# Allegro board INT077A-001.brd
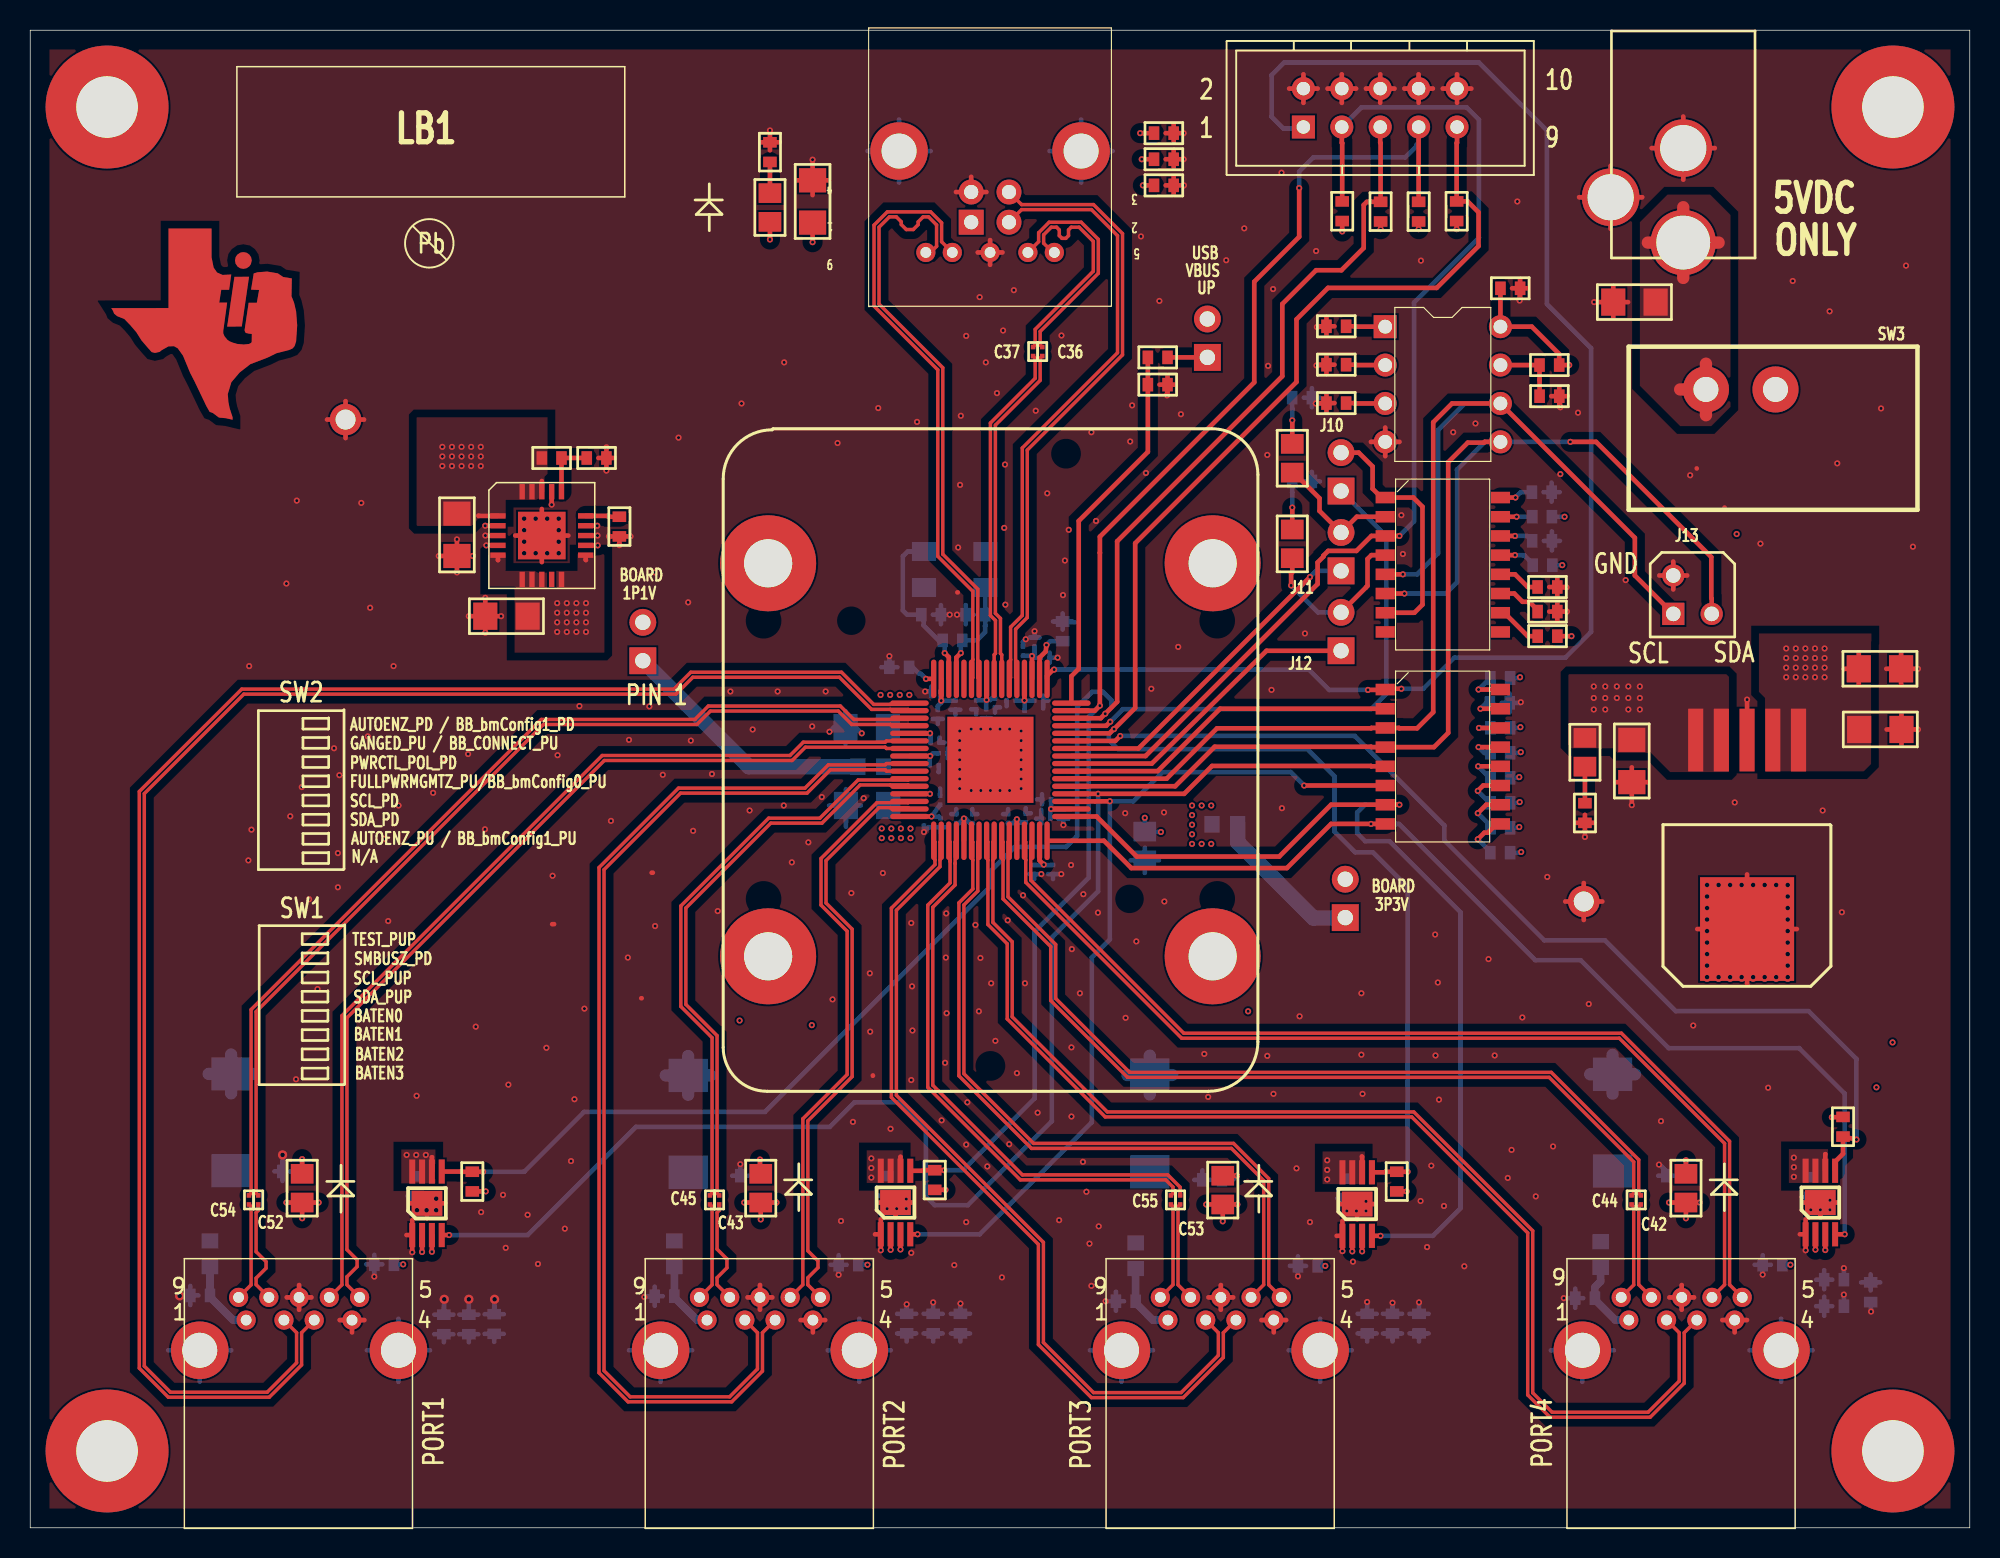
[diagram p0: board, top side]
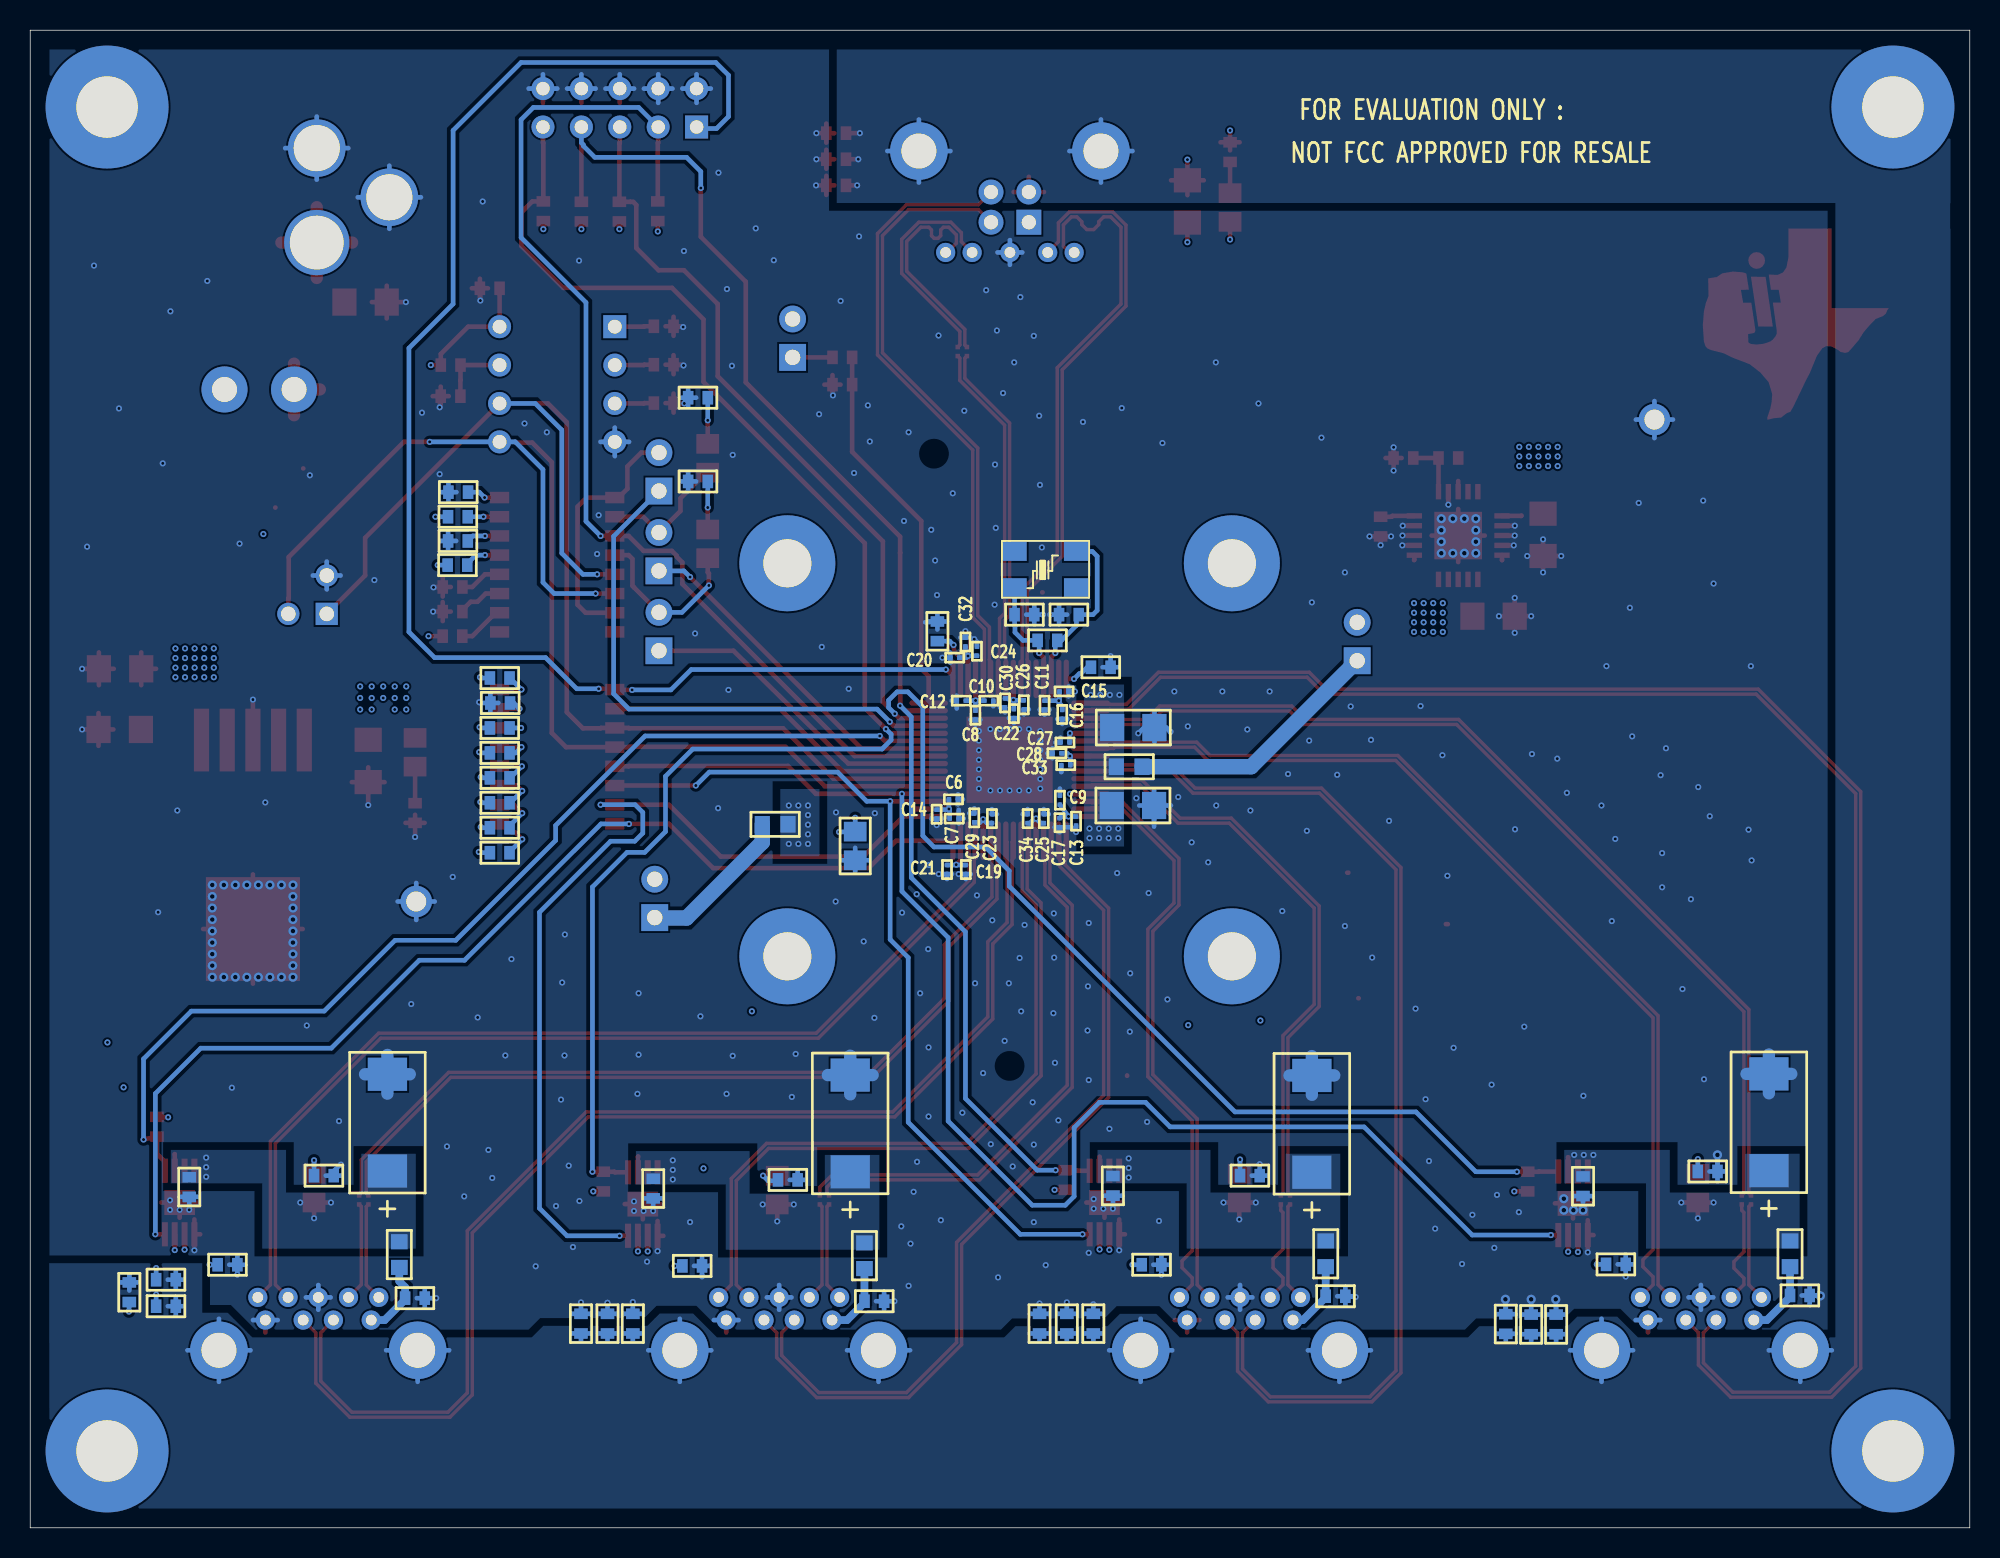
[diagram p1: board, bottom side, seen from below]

Outline 128.27 x 99.06 mm; copper layers: TOP, L2_GND, L3_VCC, BOTTOM. Coordinates in mm from the lower left corner of the outline.
Outline path: 0,99.06 0,0 128.27,0 128.27,99.06 0,99.06

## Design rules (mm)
net group DIFFPAIR0: nets USB_DM_UP USB_DP_UP
net group DIFFPAIR2: nets CAP_UP_TXM CAP_UP_TXP
net group DIFFPAIR3: nets USB_SSTXM_UP USB_SSTXP_UP
net group DIFFPAIR4: nets CAP_DN_TXM1 CAP_DN_TXP1
net group DIFFPAIR5: nets USB_SSTXM_DN1 USB_SSTXP_DN1
net group DIFFPAIR6: nets USB_SSRXM_DN1 USB_SSRXP_DN1
net group DIFFPAIR7: nets USB_DM_DN1 USB_DP_DN1
net group DIFFPAIR8: nets CAP_DN_TXM2 CAP_DN_TXP2
net group DIFFPAIR9: nets USB_SSTXM_DN2 USB_SSTXP_DN2
net group DIFFPAIR10: nets USB_SSRXM_DN2 USB_SSRXP_DN2
net group DIFFPAIR11: nets USB_DM_DN2 USB_DP_DN2
net group DIFFPAIR12: nets CAP_DN_TXM3 CAP_DN_TXP3
net group DIFFPAIR13: nets USB_SSTXM_DN3 USB_SSTXP_DN3
net group DIFFPAIR14: nets USB_SSRXM_DN3 USB_SSRXP_DN3
net group DIFFPAIR15: nets USB_DM_DN3 USB_DP_DN3
net group DIFFPAIR16: nets CAP_DN_TXM4 CAP_DN_TXP4
net group DIFFPAIR17: nets USB_SSTXM_DN4 USB_SSTXP_DN4
net group DIFFPAIR18: nets USB_SSRXM_DN4 USB_SSRXP_DN4
net group DIFFPAIR19: nets USB_DM_DN4 USB_DP_DN4
net group DIFFPAIR20: nets USB_SSRXN_UP USB_SSRXP_UP

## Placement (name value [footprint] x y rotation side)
C1  18pF  [0402]  63.17 60.4 180 bottom
C2  18pF  [0402]  58.93 60.4 0 bottom
C3  1uF  [0402]  68.28 58.65 90 bottom
C4  0.1uF  [0402]  97.23 81.99 0 top
C5  1uF  [0805]  73.71 46.05 270 bottom
C6  0.001uF  [0201]  67.51 48.18 180 bottom
C7  0.01uF  [0201]  67.46 46.91 180 bottom
C8  0.1uF  [0201]  65.76 54.05 270 bottom
C9  0.001uF  [0201]  60.17 47.83 90 bottom
C10  0.01uF  [0201]  65.18 54.71 180 bottom
C11  0.1uF  [0201]  61.19 54.71 270 bottom
C12  0.001uF  [0201]  66.4 54.71 0 bottom
C13  0.01uF  [0201]  59.11 47.04 270 bottom
C14  0.1uF  [0201]  68.33 47.5 270 bottom
C15  0.001uF  [0201]  60.2 55.32 180 bottom
C16  0.01uF  [0201]  60.02 54.1 270 bottom
C17  0.1uF  [0201]  60.2 46.94 270 bottom
C18  10uF  [1206]  56.72 52.93 180 bottom
C19  0.001uF  [0201]  66.4 43.84 270 bottom
C20  0.01uF  [0201]  66.83 57.56 0 bottom
C21  0.1uF  [0201]  67.64 43.84 270 bottom
C22  0.001uF  [0201]  63.22 54.15 270 bottom
C23  0.01uF  [0201]  64.67 46.61 90 bottom
C24  0.1uF  [0201]  65.66 57.68 90 bottom
C25  0.001uF  [0201]  61.24 46.61 90 bottom
C26  0.01uF  [0201]  62.56 54.74 270 bottom
C27  0.1uF  [0201]  59.54 51.94 0 bottom
C28  0.001uF  [0201]  60.07 51.23 0 bottom
C29  0.01uF  [0201]  65.84 46.66 90 bottom
C30  0.1uF  [0201]  63.8 54.86 270 bottom
C31  10uF  [1206]  56.74 47.78 180 bottom
C32  0.001uF  [0201]  66.42 58.29 90 bottom
C33  0.01uF  [0201]  59.49 50.44 0 bottom
C34  0.1uF  [0201]  62.31 46.61 90 bottom
C35  10uF  [1206]  51.74 86.33 90 top
C36  0.1uF 0201  [0201]  66.32 78.1 270 top
C37  0.1uF 0201  [0201]  66.93 78.1 270 top
C38  0.1uF  [0402]  74.32 92.25 0 top
C39  0.001uF  [0402]  74.32 90.53 0 top
C40  0.1uF  [0402]  103.48 15.19 180 bottom
C41  0.1uF  [0402]  42.6 15.32 180 bottom
C42  0.1uF 0201  [0201]  106.51 21.39 90 top
C43  0.1uF 0201  [0201]  45.56 21.39 90 top
C44  0.1uF 0201  [0201]  105.91 21.39 90 top
C45  0.1uF 0201  [0201]  44.95 21.39 90 top
C46  0.1uF  [0402]  118.64 14.66 0 bottom
C47  0.001uF  [0402]  118.64 16.41 0 bottom
C48  0.1uF  [0402]  57.96 12.85 90 bottom
C49  0.001uF  [0402]  59.72 12.85 90 bottom
C50  0.1uF  [0402]  11.89 15.37 180 bottom
C51  0.1uF  [0402]  73.1 14.99 180 bottom
C52  0.1uF 0201  [0201]  15.08 21.39 90 top
C53  0.1uF 0201  [0201]  76.05 21.39 90 top
C54  0.1uF 0201  [0201]  14.47 21.39 90 top
C55  0.1uF 0201  [0201]  75.44 21.39 90 top
C56  0.1uF  [0402]  30.68 12.83 90 bottom
C57  0.001uF  [0402]  29.01 12.8 90 bottom
C58  0.1uF  [0402]  90.09 12.85 90 bottom
C59  0.001uF  [0402]  88.42 12.85 90 bottom
C61  10uF  [1206]  107.49 81.08 180 top
C66  0.1uF  [0402]  24.05 17.42 180 bottom
C67  10uF  [1206]  120.95 52.81 0 top
C68  10uF  [1206]  105.92 52.12 270 top
C69  0.1uF  [0402]  25.58 23.24 270 bottom
C70  150uF  [7343]  13.28 23.62 90 bottom
C71  150uF  [7343]  43.51 23.52 90 bottom
C72  0.1uF  [0402]  56.67 23.27 270 bottom
C73  10uF  [1206]  32.89 60.3 180 top
C74  10uF  [1206]  28.22 67.08 270 top
C75  0.1uF  [0402]  54.76 17.4 180 bottom
C76  150uF  [7343]  74.04 23.55 90 bottom
C77  0.1uF  [0402]  87.07 23.09 270 bottom
C78  0.1uF  [0402]  85.14 17.32 180 bottom
C79  150uF  [7343]  104.65 23.6 90 bottom
C80  0.1uF  [0402]  117.75 23.19 270 bottom
C81  0.1uF  [0402]  115.87 17.4 180 bottom
C82  10uF  [1206]  120.93 56.82 0 top
D1  LED Green 0805  [0805]  48.92 86.39 90 top
D2  LED-DNI  [0805]  83.46 64.13 90 top
D3  LED-DNI  [0805]  83.46 69.8 90 top
D4  LED Green 0805  [0805]  102.82 52.25 270 top
D5  LED Green 0805  [0805]  17.98 21.51 90 top
D6  LED Green 0805  [0805]  48.31 21.51 90 top
D7  LED Green 0805  [0805]  78.87 21.39 90 top
D8  LED Green 0805  [0805]  109.5 21.51 90 top
FB1  220 @ 100MHZ  [0603]  78.16 46.53 0 bottom
FB2  220 @ 100MHZ  [0603]  56.44 50.34 180 bottom
FB3  220 @ 100MHZ  [0603]  103.86 17.22 90 bottom
FB4  220 @ 100MHZ  [0603]  42.6 17.27 90 bottom
FB5  220 @ 100MHZ  [0603]  11.89 17.27 90 bottom
FB6  220 @ 100MHZ  [0603]  73.1 17.14 90 bottom
GND1  TEST POINT  [TESTLOOP]  20.85 73.3 0 top
GND2  TEST POINT  [TESTLOOP]  102.74 41.43 0 top
J1  USB3_TYPEB_CONNECTOR  [USB3_TYPEB_AK4AA009]  62.23 86.36 180 top
J2  USB3_TYPEA_CONNECTOR  [USB3_TYPEA]  109.22 15.24 0 top
J3  USB3_TYPEA_CONNECTOR  [USB3_TYPEA]  48.26 15.24 0 top
J4  USB3_TYPEA_CONNECTOR  [USB3_TYPEA]  17.78 15.24 0 top
J5  USB3_TYPEA_CONNECTOR  [USB3_TYPEA]  78.74 15.24 0 top
J6  2.1mm x 5.5mm  [PJ-202AH]  109.32 85.01 180 top
J7  Header 1x2  [HDR_2X1]  86.97 40.36 0 top
J8  Header 1x2  [HDR_2X1]  77.85 77.42 0 top
J9  Header 1x2  [HDR_2X1]  40.51 57.35 0 top
J10  Header 1x2  [HDR_2X1]  86.69 68.58 0 top
J11  Header 1x2  [HDR_2X1]  86.69 63.3 0 top
J12  Header 1x2  [HDR_2X1]  86.69 58.01 0 top
J13  Header 1x2  [HDR_THVT_3PIN_100]  108.66 62.99 0 top
JP6  Conn 2x5 shroud  [EPRT-CONN-00002-0001]  84.2 92.66 0 top
NOREF  -  []  0 0 90 top
NOREF#2  -  [unnamed#2]  5.08 93.98 0 top
NOREF#3  -  []  11.35 79.3 0 top
NOREF#4  -  [unnamed#2]  5.08 5.08 0 top
NOREF#5  -  []  0 99.06 0 top
NOREF#6  -  [unnamed#2]  123.19 5.08 0 top
NOREF#7  -  [unnamed#2]  123.19 93.98 0 top
R1  1M  [0402]  61.65 58.7 180 bottom
R2  90.9K  [0402]  73.91 77.42 0 top
R3  10K  [0402]  73.91 75.62 0 top
R4  1K  [0402]  96.57 52.91 0 bottom
R5  1K  [0402]  96.57 51.26 0 bottom
R6  4.7K  [0402]  96.57 49.61 0 bottom
R7  4.7K  [0402]  96.57 47.96 0 bottom
R8  4.7K  [0402]  96.57 46.3 0 bottom
R9  4.7K  [0402]  96.57 44.65 0 bottom
R10  NOPOP  [0402]  101.12 76.91 180 top
R11  1K  [0402]  85.72 79.48 0 top
R12  1K  [0402]  85.72 76.94 0 top
R13  1K  [0402]  85.72 74.4 0 top
R14  1K  [0402]  99.82 74.85 0 top
R15  1M  [0402]  74.32 88.8 0 top
R16  330  [0402]  48.92 90.35 90 top
R17  1M  [0402]  121.72 16.23 270 bottom
R18  1M  [0402]  61.52 12.85 90 bottom
R19  1M  [0402]  27.36 12.8 90 bottom
R20  1M  [0402]  91.85 12.85 90 bottom
R21  9.53K  [0402]  56.82 56.92 0 bottom
R22  1K  [0402]  96.57 56.21 0 bottom
R23  1K  [0402]  99.31 68.5 0 bottom
R24  1K  [0402]  97.84 54.56 180 bottom
R25  1K  [0402]  99.34 66.88 0 bottom
R26  10K  [0402]  29.24 22.25 90 top
R27  10K  [0402]  59.82 22.35 90 top
R28  330  [0402]  102.82 47.93 270 top
R29  10K  [0402]  90.37 22.25 90 top
R30  330  [0402]  17.98 23.57 180 bottom
R31  330  [0402]  48.26 23.29 180 bottom
R32  NOPOP  [0402]  38.96 66.88 270 top
R33  1.87K  [0402]  33.83 70.76 0 top
R34  4.99K  [0402]  36.8 70.76 0 top
R35  330  [0402]  78.82 23.01 180 bottom
R36  10K  [0402]  119.89 27.18 270 top
R37  330  [0402]  109.5 23.29 180 bottom
R38  1K  [0402]  99.36 63.68 0 bottom
R39  1K  [0402]  100.63 65.28 180 bottom
R40  330 - DNI  [0402]  84.76 74.75 180 bottom
R41  330 - DNI  [0402]  84.76 69.22 180 bottom
R42  NOPOP  [0402]  86.77 86.44 90 top
R43  NOPOP  [0402]  89.31 86.41 90 top
R44  NOPOP  [0402]  91.82 86.41 90 top
R45  NOPOP  [0402]  94.34 86.44 90 top
R46  1K  [0402]  100.99 60.6 180 top
R47  1K  [0402]  100.99 62.23 180 top
R48  1K  [0402]  99.69 58.98 0 top
SW1  8-POS 50-MIL SMT  [TDA08H0SK1]  93.42 51 270 top
SW2  8-POS 50-MIL SMT  [TDA08H0SK1]  93.42 63.7 270 top
SW3  L101011MS02Q  [L101_SWITCH]  111.02 70.97 270 top
U1  TUSB8044  [GEM050-0064BJ02]  63.5 50.8 0 top
U2  AT24C04  [DIP8]  89.61 79.45 0 top
U4  TPS7A4533  [KTT_6PIN]  118.69 55.02 270 top
U6  TPS74801RGW  [RGW20]  33.83 65.63 0 top
U7  TPS2001C  [DGN8]  26.24 21.46 90 top
U8  TPS2001C  [DGN8]  57.23 21.51 90 top
U9  TPS2001C  [DGN8]  87.76 21.41 90 top
U10  TPS2001C  [DGN8]  118.39 21.51 90 top
Y1  ECS-24MHZ  [ECX-53B]  61.32 63.3 180 bottom

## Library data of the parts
C1-C59 C61 C66-C69 C72-C75 C77 C78 C80-C82 = CAP NP
C70 C71 C76 C79 = CAPACITOR POL
D1-D8 = DIODE
FB1-FB6 = FERRITE BEAD
GND1 GND2 = Test Point Small
J1 = USB3_TYPEB_CONNECTOR
J2-J5 = USB3_TYPEA_CONNECTER
J6 = BNC_2
J7-J12 = HDR2X1 M .1
J13 = HDR2X1 M _0.1
JP6 = eprt-conn-00002-0000
R1-R48 = R
SW1 SW2 = SW DIP-8/SM_0
SW3 = SW SPST
U1 = TUSB8040_41
U2 = AT24C04: Tolerance: ***; User Part Number: ***
U4 = TPS79633KTT_2
U6 = TPS74801RGW_1
U7-U10 = TPS2560DRC_3
Y1 = ECS-25MHZ

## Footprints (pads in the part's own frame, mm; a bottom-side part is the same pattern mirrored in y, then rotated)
0201
  rect 0.3x0.3 smd: 1(0,0) 2(0.599,0)
0402
  rect 0.701x0.899 smd: 1(0,0) 2(1.3,0)
0603
  rect 1.001x1.1 smd: 1(0,0) 2(1.699,0)
0805
  rect 1.3x1.501 smd: 1(0,0) 2(1.9,0)
1206
  rect 1.6x1.801 smd: 1(0,0) 2(2.799,0)
7343
  rect 2.2x2.601 smd: 1(0,0) 2(6.401,0)
DGN8
  rect 1.6x0.399 smd: 1(-2.101,0.975) 2(-2.101,0.325) 3(-2.101,-0.325) 4(-2.101,-0.975) 5(2.101,-0.975) 6(2.101,-0.325) 7(2.101,0.325) 8(2.101,0.975)
  rect 1.651x2.032 smd: 9(0,0)
DIP8
  rect 1.524x1.524 hole 0.914: 1(0,0)
  round 1.524 hole 0.914: 2(0,-2.54) 3(0,-5.08) 4(0,-7.62) 5(7.62,-7.62) 6(7.62,-5.08) 7(7.62,-2.54) 8(7.62,0)
ECX-53B
  rect 1.6x1.245 smd: 1(-1.854,-1.105) 2(2.21,-1.105) 3(2.21,1.283) 4(-1.854,1.283)
EPRT-CONN-00002-0001
  rect 1.524x1.524 hole 0.889: 1(0,0)
  round 1.524 hole 0.889: 2(0,2.54) 3(2.54,0) 4(2.54,2.54) 5(5.08,0) 6(5.08,2.54) 7(7.62,0) 8(7.62,2.54) 9(10.16,0) 10(10.16,2.54)
GEM050-0064BJ02
  round 6.35 hole 3.18 unplated: (-14.699,13) (-14.699,-13) (14.699,13) (14.699,-13)
  round 0 hole 1.549 unplated: (0,-20.249) (5.001,20.249)
  oval 2.55x0.351 smd: 1(-5.354,3.749) 2(-5.354,3.251) 3(-5.354,2.751) 4(-5.354,2.25) 5(-5.354,1.75) 6(-5.354,1.25) 7(-5.354,0.749) 8(-5.354,0.249) 9(-5.354,-0.249) 10(-5.354,-0.749) 11(-5.354,-1.25) 12(-5.354,-1.75) 13(-5.354,-2.25) 14(-5.354,-2.751) 15(-5.354,-3.251) 16(-5.354,-3.749) 33(5.354,-3.749) 34(5.354,-3.251) 35(5.354,-2.751) 36(5.354,-2.25) 37(5.354,-1.75) 38(5.354,-1.25) 39(5.354,-0.749) 40(5.354,-0.249) 41(5.354,0.249) 42(5.354,0.749) 43(5.354,1.25) 44(5.354,1.75) 45(5.354,2.25) 46(5.354,2.751) 47(5.354,3.251) 48(5.354,3.749)
  oval 0.351x2.55 smd: 17(-3.749,-5.354) 18(-3.251,-5.354) 19(-2.751,-5.354) 20(-2.25,-5.354) 21(-1.75,-5.354) 22(-1.25,-5.354) 23(-0.749,-5.354) 24(-0.249,-5.354) 25(0.249,-5.354) 26(0.749,-5.354) 27(1.25,-5.354) 28(1.75,-5.354) 29(2.25,-5.354) 30(2.751,-5.354) 31(3.251,-5.354) 32(3.749,-5.354) 49(3.749,5.354) 50(3.251,5.354) 51(2.751,5.354) 52(2.25,5.354) 53(1.75,5.354) 54(1.25,5.354) 55(0.749,5.354) 56(0.249,5.354) 57(-0.249,5.354) 58(-0.749,5.354) 59(-1.25,5.354) 60(-1.75,5.354) 61(-2.25,5.354) 62(-2.751,5.354) 63(-3.251,5.354) 64(-3.749,5.354)
  rect 5.7x5.7 smd: 65(0,0)
HDR_2X1
  rect 1.778x1.778 hole 1.016: 1(0,0)
  round 1.778 hole 1.016: 2(0,2.54)
HDR_THVT_3PIN_100
  rect 1.473x1.473 hole 0.965: 1(0,-2.54)
  round 1.473 hole 0.965: 2(0,0) 3(2.54,-2.54)
KTT_6PIN
  rect 4.15x1.001 smd: 1(2.911,-1.75) 2(2.911,-3.449) 3(2.911,-5.151) 4(2.911,-6.85) 5(2.911,-8.55)
  rect 6.861x6.22 smd: 6(15.41,-5.151)
L101_SWITCH
  round 3.048 hole 1.651: 1(-4.331,-0.201) 2(-4.331,4.399)
PJ-202AH
  round 4.318 hole 3.556: 1(0,0)
  round 3.81 hole 3.048: 2(4.801,-2.997) 3(0,-6.248)
RGW20
  rect 1.016x0.356 smd: 1(-2.901,1.3) 2(-2.901,0.65) 3(-2.901,0) 4(-2.901,-0.65) 5(-2.901,-1.3) 11(2.901,-1.3) 12(2.901,-0.65) 13(2.901,0) 14(2.901,0.65) 15(2.901,1.3)
  rect 0.356x1.016 smd: 6(-1.3,-2.901) 7(-0.65,-2.901) 8(0,-2.901) 9(0.65,-2.901) 10(1.3,-2.901) 16(1.3,2.901) 17(0.65,2.901) 18(0,2.901) 19(-0.65,2.901) 20(-1.3,2.901)
  rect 3.15x3.15 smd: 21(0,0)
TDA08H0SK1
  rect 0.762x1.27 smd: 1(-4.445,-3.81) 2(-3.175,-3.81) 3(-1.905,-3.81) 4(-0.635,-3.81) 5(0.635,-3.81) 6(1.905,-3.81) 7(3.175,-3.81) 8(4.445,-3.81) 9(4.445,3.81) 10(3.175,3.81) 11(1.905,3.81) 12(0.635,3.81) 13(-0.635,3.81) 14(-1.905,3.81) 15(-3.175,3.81) 16(-4.445,3.81)
TESTLOOP
  round 2.083 hole 1.321: 1(0,0)
unnamed#2
  round 8.128 hole 4.064: (0,0)
USB3_TYPEA
  round 1.27 hole 0.711: 1(-3.5,-1.501) 2(-1.001,-1.501) 3(1.001,-1.501) 4(3.5,-1.501) 5(4,0) 6(1.999,0) 7(0,0) 8(-1.999,0) 9(-4,0)
  round 3.81 hole 2.311: 10(-6.571,-3.5) 11(6.571,-3.5)
USB3_TYPEB_AK4AA009
  rect 1.651x1.651 hole 0.94: 1(0,0)
  round 1.651 hole 0.94: 2(-2.499,0) 3(-2.499,-1.999) 4(0,-1.999)
  round 1.27 hole 0.711: 5(-5.499,1.999) 6(-3.749,1.999) 7(-1.25,1.999) 8(1.25,1.999) 9(3,1.999)
  round 3.81 hole 2.311: 10(-7.269,-4.709) 11(4.77,-4.709)

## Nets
GND: C1.2 C2.2 C3.2 C4.2 C5.2 C6.2 C7.2 C8.2 C9.2 C10.2 C11.2 C12.2 C13.2 C14.2 C15.2 C16.2 C17.2 C18.2 C19.2 C20.2 C21.2 C22.2 C23.2 C24.2 C25.2 C26.2 C27.2 C28.2 C29.2 C30.2 C31.2 C32.2 C33.2 C34.2 C35.2 C38.2 C39.2 C40.2 C41.2 C46.2 C47.2 C48.2 C49.2 C50.2 C51.2 C56.2 C57.2 C58.2 C59.2 C61.2 C66.2 C67.2 C68.2 C69.2 C70.2 C71.2 C72.2 C73.2 C74.2 C75.2 C76.2 C77.2 C78.2 C79.2 C80.2 C81.2 C82.2 GND1.1(TP) GND2.1(TP) J1.4(GND#4) J1.7(GND#7) J2.4(GND#4) J2.7(GND#7) J3.4(GND#4) J3.7(GND#7) J4.4(GND#4) J4.7(GND#7) J5.4(GND#4) J5.7(GND#7) J6.2(S) J6.3(SW) J13.2 JP6.2 JP6.4 JP6.6 JP6.8 JP6.10 R3.2 R11.1 R12.1 R13.1 R14.2 R15.2 R16.2 R17.2 R18.2 R19.2 R20.2 R21.1 R23.2 R24.1 R28.2 R30.2 R31.2 R32.2 R34.2 R35.2 R37.2 R39.1 R40.1 R41.1 R46.1 R47.1 U1.65(PPAD) U2.4(GND) U4.3(GND#3) U4.6(GND#6) U6.2(NC1) U6.3(NC2) U6.4(NC3) U6.12(GND#12) U6.13(NC4) U6.14(NC5) U6.17(NC6) U6.21(GND#21) U7.1(GND) U7.9(PAD) U8.1(GND) U8.9(PAD) U9.1(GND) U9.9(PAD) U10.1(GND) U10.9(PAD)
GND_EARTH: C38.1 C39.1 C46.1 C47.1 C48.1 C49.1 C56.1 C57.1 C58.1 C59.1 J1.10(SHIELD0) J1.11(SHIELD1) J2.10(SHIELD0) J2.11(SHIELD1) J3.10(SHIELD0) J3.11(SHIELD1) J4.10(SHIELD0) J4.11(SHIELD1) J5.10(SHIELD0) J5.11(SHIELD1) R15.1 R17.1 R18.1 R19.1 R20.1
VBUS_DS1: C50.1 FB5.1 J4.1(VBUS)
VBUS_DS2: C41.1 FB4.1 J3.1(VBUS)
VBUS_DS3: C51.1 FB6.1 J5.1(VBUS)
VBUS_DS4: C40.1 FB3.1 J2.1(VBUS)
VDD11: C18.1 C19.1 C20.1 C21.1 C22.1 C23.1 C24.1 C25.1 C26.1 C27.1 C28.1 C29.1 C30.1 C31.1 C32.1 C33.1 C34.1 FB2.1 U1.5(VDD11#5) U1.8(VDD11#8) U1.13(VDD11#13) U1.21(VDD11#21) U1.28(VDD11#28) U1.31(VDD11#31) U1.51(VDD11#51) U1.57(VDD11#57)
VDD33: C5.1 C6.1 C7.1 C8.1 C9.1 C10.1 C11.1 C12.1 C13.1 C14.1 C15.1 C16.1 C17.1 FB1.1 U1.16(VDD33#16) U1.34(VDD33#34) U1.52(VDD33#52) U1.63(VDD33#63)
1P1V_FB: R33.2 R34.1 U6.16(FB)
1P1V_SS: R32.1 U6.15(SS)
AUTOENZ/BB_BMCONFIG1: J10.1 U1.45(AUTOENZ_HS_SUSPEND)
AUTOENZ/BB_BMCONFIG1_2: J10.2 SW2.1(A1) SW2.7(A7)
AUTOENZ_PD/BB_BMCONFIG1_PD: R23.1 SW2.16(B1)
AUTOENZ_PU/BB_BMCONFIG1_PU: R48.1 SW2.10(B7)
BATEN0: R6.1 SW1.12(B5)
BATEN1: R7.1 SW1.11(B6)
BATEN2: R8.1 SW1.10(B7)
BATEN3: R9.1 SW1.9(B8)
BOARD_1P1V: C74.1 J9.2 R33.1 U6.1(OUT1) U6.18(OUT2) U6.19(OUT3) U6.20(OUT4)
BOARD_3P3V: C4.1 C68.1 C73.1 D4.1(A) J7.2 R4.2 R5.2 R6.2 R7.2 R8.2 R9.2 R10.1 R22.2 R25.2 R26.1 R27.1 R29.1 R36.1 R38.2 R42.1 R43.1 R44.1 R45.1 R48.2 U2.8(VCC) U4.4(OUT) U4.5(SENSE) U6.5(IN1) U6.6(IN2) U6.7(IN3) U6.8(IN4) U6.10(BIAS) U6.11(EN)
BOARD_5V: C66.1 C67.1 C75.1 C78.1 C81.1 C82.1 SW3.2 U4.1(SHDN/) U4.2(IN) U7.2(IN#2) U7.3(IN#3) U8.2(IN#2) U8.3(IN#3) U9.2(IN#2) U9.3(IN#3) U10.2(IN#2) U10.3(IN#3)
CAP_DN_TXM1: C52.1 J4.8(SSTXN)
CAP_DN_TXM2: C43.1 J3.8(SSTXN)
CAP_DN_TXM3: C53.1 J5.8(SSTXN)
CAP_DN_TXM4: C42.1 J2.8(SSTXN)
CAP_DN_TXP1: C54.1 J4.9(SSTXP)
CAP_DN_TXP2: C45.1 J3.9(SSTXP)
CAP_DN_TXP3: C55.1 J5.9(SSTXP)
CAP_DN_TXP4: C44.1 J2.9(SSTXP)
CAP_UP_TXM: C36.1 J1.5(SSTXN)
CAP_UP_TXP: C37.1 J1.6(SSTXP)
DN1_VBUS: C69.1 C70.1 D5.1(A) FB5.2 U7.6(OUT#6) U7.7(OUT#7) U7.8(OUT#8)
DN2_VBUS: C71.1 C72.1 D6.1(A) FB4.2 U8.6(OUT#6) U8.7(OUT#7) U8.8(OUT#8)
DN3_VBUS: C76.1 C77.1 D7.1(A) FB6.2 U9.6(OUT#6) U9.7(OUT#7) U9.8(OUT#8)
DN4_VBUS: C79.1 C80.1 D8.1(A) FB3.2 U10.6(OUT#6) U10.7(OUT#7) U10.8(OUT#8)
FULLPWRMGMTZ_PUP/BB_BMCONFIG0_P: R38.1 SW2.13(B4)
FULLPWRMGMTZ_SS_UP/BB_BMCONFI_1: J12.1 U1.40(FULLPWRMGMTZ_SMBA1_SS_UP)
FULLPWRMGMTZ_SS_UP/BB_BMCONFIG0: D2.1(A) J12.2 SW2.4(A4)
GANGED_HS_UP/BB_CONNECT: J11.1 U1.42(GANGED_SMBA2_HS_UP)
GANGED_HS_UP/BB_CONNECT_2: D3.1(A) J11.2 SW2.2(A2)
GANGED_PU/BB_CONNECT_PU: R25.1 SW2.15(B2)
GRSTZ: C3.1 U1.50(GRSTN)
OVERCUR1Z_TDI: JP6.5 R26.2 R43.2 U1.46(OVRCUR1Z_TDI) U7.5(FLT)
OVERCUR2Z_TMS: JP6.7 R27.2 R44.2 U1.47(OVRCUR2Z_TMS) U8.5(FLT)
OVERCUR3Z_TCK: JP6.9 R29.2 R45.2 U1.44(OVRCUR3Z_TCK) U9.5(FLT)
OVERCUR4Z: R36.2 U1.43(OVRCUR4Z) U10.5(FLT)
PWRCTL_POL_PD: R39.2 SW2.14(B3)
PWRCTL_POL_TDO: JP6.3 R42.2 SW2.3(A3) U1.41(PWRCTL_POL_TDO)
PWRON1_BATEN1: SW1.5(A5) U1.36(PWRON1Z_BATEN1) U7.4(EN)
PWRON2_BATEN2: SW1.6(A6) U1.35(PWRON2Z_BATEN2) U8.4(EN)
PWRON3_BATEN3: SW1.7(A7) U1.33(PWRON3Z_BATEN3) U9.4(EN)
PWRON4_BATEN4: SW1.8(A8) U1.32(PWRON4Z_BATEN4) U10.4(EN)
SCL_PD: R47.2 SW2.12(B5)
SCL_PUP: R4.1 SW1.14(B3)
SCL_SMBCLK: J13.1 SW1.3(A3) SW2.5(A5) U1.38(SCL_SMBCLK) U2.6(SCLK)
SDA_PD: R46.2 SW2.11(B6)
SDA_PUP: R5.1 SW1.13(B4)
SDA_SMBDAT: J13.3 SW1.4(A4) SW2.6(A6) U1.37(SDA_SMBDAT) U2.5(SDATA)
SMBUSZ: SW1.2(A2) U1.39(SMBUSZ_SS_SUSPEND)
SMBUSZ_PD: R24.2 SW1.15(B2)
TEST_PUP: R22.1 SW1.16(B1)
TEST_TRSTZ: JP6.1 SW1.1(A1) U1.49(TEST_TRSTZ)
USB_DM_DN1: J4.2(DM) U1.2(USB_DM_DN1)
USB_DM_DN2: J3.2(DM) U1.10(USB_DM_DN2)
USB_DM_DN3: J5.2(DM) U1.18(USB_DM_DN3)
USB_DM_DN4: J2.2(DM) U1.25(USB_DM_DN4)
USB_DM_UP: J1.2(DM) U1.54(USB_DM_UP)
USB_DP_DN1: J4.3(DP) U1.1(USB_DP_DN1)
USB_DP_DN2: J3.3(DP) U1.9(USB_DP_DN2)
USB_DP_DN3: J5.3(DP) U1.17(USB_DP_DN3)
USB_DP_DN4: J2.3(DP) U1.24(USB_DP_DN4)
USB_DP_UP: J1.3(DP) U1.53(USB_DP_UP)
USB_SSRXM_DN1: J4.5(SSRXN) U1.7(USB_SSRXM_DN1)
USB_SSRXM_DN2: J3.5(SSRXN) U1.15(USB_SSRXM_DN2)
USB_SSRXM_DN3: J5.5(SSRXN) U1.23(USB_SSRXM_DN3)
USB_SSRXM_DN4: J2.5(SSRXN) U1.30(USB_SSRXM_DN4)
USB_SSRXN_UP: J1.8(SSRXN) U1.59(USB_SSRXM_UP)
USB_SSRXP_DN1: J4.6(SSRXP) U1.6(USB_SSRXP_DN1)
USB_SSRXP_DN2: J3.6(SSRXP) U1.14(USB_SSRXP_DN2)
USB_SSRXP_DN3: J5.6(SSRXP) U1.22(USB_SSRXP_DN3)
USB_SSRXP_DN4: J2.6(SSRXP) U1.29(USB_SSRXP_DN4)
USB_SSRXP_UP: J1.9(SSRXP) U1.58(USB_SSRXP_UP)
USB_SSTXM_DN1: C52.2 U1.4(USB_SSTXM_DN1)
USB_SSTXM_DN2: C43.2 U1.12(USB_SSTXM_DN2)
USB_SSTXM_DN3: C53.2 U1.20(USB_SSTXM_DN3)
USB_SSTXM_DN4: C42.2 U1.27(USB_SSTXM_DN4)
USB_SSTXM_UP: C36.2 U1.56(USB_SSTXM_UP)
USB_SSTXP_DN1: C54.2 U1.3(USB_SSTXP_DN1)
USB_SSTXP_DN2: C45.2 U1.11(USB_SSTXP_DN2)
USB_SSTXP_DN3: C55.2 U1.19(USB_SSTXP_DN3)
USB_SSTXP_DN4: C44.2 U1.26(USB_SSTXP_DN4)
USB_SSTXP_UP: C37.2 U1.55(USB_SSTXP_UP)
USB_VBUS_UP: C35.1 D1.1(A) J1.1(VBUS) J8.2
N17052812: R2.1 R3.1 U1.48(USB_VBUS)
N17181221: R10.2 R14.1 U2.7(WP)
N17181233: R11.2 U2.1(A0)
N17181243: R12.2 U2.2(A1)
N17181324: R13.2 U2.3(A2)
N17381185: D5.2(K) R30.1
N17383170: D1.2(K) R16.1
N17408350: D4.2(K) R28.1
N18334081: C2.1 R1.2 U1.62(XI) Y1.3(A3)
N18334093: C1.1 R1.1 U1.61(XO) Y1.1(A1)
N18711690: D6.2(K) R31.1
N18712170: D7.2(K) R35.1
N18712674: D8.2(K) R37.1
N18713919: R21.2 U1.64(USB_R1)
N18725733: J8.1 R2.2
N18726136: FB1.2 J7.1
N18726182: FB2.2 J9.1
N18744223: C61.1 J6.1(T) SW3.1
N187210031: D2.2(K) R41.2
N187210111: D3.2(K) R40.2

Pads without a net: SW2 8 9; U1 60; U6 9; Y1 2 4

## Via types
v1: diameter 0.406, hole 0.203, TOP to BOTTOM, 540 vias
v2: diameter 0.61, hole 0.305, TOP to BOTTOM, 51 vias

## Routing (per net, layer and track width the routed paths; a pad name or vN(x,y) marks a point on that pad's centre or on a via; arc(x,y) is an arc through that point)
GND: length 500.3
  TOP w0.305: R12.1 85.72,77.57 ; R12.1 85.72,76.31 ; R12.1 85.19,76.94 ; R12.1 v1(85.06,76.89) ; R12.1 86.26,76.94 ; U9.9 88.95,21.41 ; U9.9 87.76,20.41 ; U9.9 86.56,21.41 ; R47.1 101.52,62.23 ; R47.1 100.99,61.6 ; R47.1 v1(101.6,62.2) ; R47.1 100.99,62.86 ; R47.1 100.46,62.23 ; 100.46,60.6 R46.1 ; R46.1 100.99,59.97 ; R46.1 v1(101.63,60.6) ; R46.1 100.99,61.23 ; C38.2 75.62,92.88 ; C38.2 75.09,92.25 ; C38.2 75.62,91.62 ; C38.2 v1(76.28,92.25) ; 88.34,95.2 JP6.6 ; JP6.6 89.28,96.14 ; JP6.6 90.22,95.2 ; JP6.6 89.28,94.26 ; U4.3 v1(113.54,54.78) ; 85.72,78.85 R11.1 ; R11.1 85.19,79.48 ; R11.1 v1(85.09,79.43) ; R11.1 85.72,80.11 ; R11.1 86.26,79.48 ; J6.2 106.61,88.01 ; J6.2 104.52,85.93 ; J6.2 104.52,90.1 ; J6.2 102.44,88.01 ; 51.74,88.15 C35.2 ; C35.2 v1(51.74,90.5) ; C35.2 52.82,89.13 ; C35.2 50.66,89.13 ; U10.1 117.41,20.39 ; U10.1 117.03,19.41 ; U10.1 v1(117.41,18.35) ; U8.1 v1(56.25,18.35) ; U8.1 55.87,19.41 ; U8.1 56.25,20.39 ; C82.2 123.73,57.9 ; C82.2 122.75,56.82 ; C82.2 v1(124.84,56.82) ; C82.2 123.73,55.74 ; R28.2 102.82,47.16 ; R28.2 102.19,46.63 ; R28.2 103.45,46.63 ; R28.2 v1(102.82,45.69) ; 91.82,94.26 JP6.8 ; JP6.8 91.82,96.14 ; JP6.8 90.88,95.2 ; JP6.8 92.76,95.2 ; 88.67,71.83 U2.4 ; U2.4 90.55,71.83 ; U2.4 89.61,70.89 ; U2.4 89.61,72.77 ; R3.2 75.21,76.25 ; R3.2 v1(75.18,74.9) ; R3.2 75.75,75.62 ; R3.2 75.21,74.99 ; R3.2 74.68,75.62 ; R32.2 v1(38.96,65) ; R32.2 v1(38.27,65.58) ; R32.2 v1(39.7,65.58) ; C74.2 v1(28.22,63.2) ; C74.2 v1(29.27,64.28) ; C74.2 v1(28.22,65.38) ; C74.2 v1(27.02,64.28) ; JP6.2 85.14,95.2 ; JP6.2 83.26,95.2 ; JP6.2 84.2,96.14 ; JP6.2 84.2,94.26 ; 57.23,20.51 U8.9 ; U8.9 56.03,21.51 ; U8.9 58.42,21.51 ; J2.4 113.54,13.74 ; J2.4 112.72,12.92 ; J2.4 111.9,13.74 ; 107.74,62.99 J13.2 ; J13.2 109.58,62.99 ; J13.2 108.66,62.08 ; J13.2 108.66,63.91 ; 34.65,39.93 34.52,39.93 ; 48.26,14.42 J3.7 ; J3.7 49.08,15.24 ; J3.7 47.44,15.24 ; J3.7 48.26,16.06 ; 48.29,91.65 R16.2 ; R16.2 48.92,91.12 ; R16.2 49.55,91.65 ; R16.2 v1(48.92,92.43) ; J4.4 22.1,13.74 ; J4.4 21.28,12.92 ; J4.4 20.46,13.74 ; J4.7 18.6,15.24 ; J4.7 17.78,16.06 ; J4.7 17.78,14.42 ; J4.7 16.96,15.24 ; 104.84,49.32 C68.2 ; C68.2 107,49.32 ; C68.2 v1(105.92,47.8) ; C68.2 105.92,50.3 ; GND1.1 20.85,74.53 ; GND1.1 19.63,73.3 ; GND1.1 22.08,73.3 ; GND1.1 20.85,72.08 ; R34.2 v1(38.11,69.93) ; R34.2 37.57,70.76 ; R34.2 38.64,70.76 ; R34.2 v1(38.11,71.47) ; U6.17 v1(34.48,67.68) ; 110.21,70.07 110.22,70.07 ; R13.1 86.26,74.4 ; R13.1 85.72,75.03 ; R13.1 85.72,73.77 ; R13.1 v1(85.01,74.37) ; R13.1 85.19,74.4 ; J1.7 64.3,84.36 ; J1.7 63.48,83.55 ; J1.7 63.48,85.18 ; J1.7 62.66,84.36 ; U9.1 v1(86.78,18.3) ; U9.1 86.78,20.29 ; U9.1 86.4,19.31 ; J6.3 109.32,93.35 ; J6.3 107.24,91.26 ; J6.3 109.32,89.18 ; J6.3 111.41,91.26 ; 93.42,95.2 JP6.10 ; JP6.10 94.36,94.26 ; JP6.10 95.3,95.2 ; JP6.10 94.36,96.14 ; J2.7 109.22,16.06 ; J2.7 108.4,15.24 ; J2.7 110.04,15.24 ; J2.7 109.22,14.42 ; JP6.4 87.68,95.2 ; JP6.4 86.74,96.14 ; JP6.4 86.74,94.26 ; JP6.4 85.8,95.2 ; 55.73,29.9 55.73,29.92 ; U6.21 33.83,67.39 ; U6.21 32.08,65.63 ; U6.21 33.83,63.88 ; U6.21 35.59,65.63 ; C61.2 v1(103.43,81.08) ; C61.2 104.69,82.16 ; C61.2 104.69,79.99 ; C61.2 105.67,81.08 ; U6.12 v1(37.53,64.98) ; C39.2 v1(76.28,90.53) ; C39.2 75.09,90.53 ; C39.2 75.62,89.9 ; C39.2 75.62,91.16 ; 78.74,14.42 J5.7 ; J5.7 77.92,15.24 ; J5.7 78.74,16.06 ; J5.7 79.56,15.24 ; U4.6 113.54,43.22 ; U4.6 116.83,39.61 ; U4.6 113.54,35.99 ; U4.6 110.25,39.61 ; C4.2 99.06,81.99 ; C4.2 v1(98.5,81.18) ; C4.2 98,81.99 ; C4.2 98.53,82.62 ; C4.2 98.53,81.36 ; 82.24,12.92 J5.4 ; J5.4 81.42,13.74 ; J5.4 83.06,13.74 ; 75.09,88.8 R15.2 ; R15.2 75.62,89.43 ; R15.2 v1(76.3,88.8) ; R15.2 75.62,88.17 ; U10.9 119.59,21.51 ; U10.9 118.39,20.51 ; U10.9 117.19,21.51 ; C67.2 v1(124.84,52.81) ; C67.2 122.77,52.81 ; C67.2 123.75,51.72 ; C67.2 123.75,53.89 ; U6.4 v1(30.16,64.98) ; 102.74,40.21 GND2.1 ; GND2.1 101.52,41.43 ; GND2.1 103.96,41.43 ; GND2.1 102.74,42.65 ; 50.94,13.74 J3.4 ; J3.4 51.76,12.92 ; J3.4 52.58,13.74 ; J1.4 63.24,88.36 ; J1.4 61.22,88.36 ; J1.4 62.23,89.36 ; R14.2 101.65,74.85 ; R14.2 100.59,74.85 ; R14.2 v1(101.19,74.12) ; R14.2 101.12,75.48 ; R14.2 101.12,74.22 ; 41.1,43.33 41.17,43.33 ; C73.2 v1(30.09,61.51) ; C73.2 v1(30.09,59.2) ; C73.2 v1(29.01,60.3) ; C73.2 v1(31.14,60.3) ; U6.13 v1(37.52,65.63) ; 40.41,35.03 40.44,35.03 ; 112.06,67.49 112.06,67.48 ; 24.88,19.36 U7.1 ; U7.1 v1(25.26,18.22) ; U7.1 25.26,20.34 ; U6.2 v1(30.09,66.28) ; 61.32,61.87 61.34,61.87 ; U6.14 v1(37.5,66.28) ; U7.9 27.43,21.46 ; U7.9 25.04,21.46 ; U7.9 26.24,20.46 ; U6.3 v1(30.1,65.63)
  L2_GND w0.305: J1.4 63.24,88.36 ; J1.4 61.22,88.36 ; J1.4 62.23,89.36 ; J6.3 111.41,91.26 ; J6.3 109.32,93.35 ; J6.3 107.24,91.26 ; J6.3 109.32,89.18 ; JP6.6 89.28,96.14 ; JP6.6 90.22,95.2 ; JP6.6 88.34,95.2 ; JP6.6 89.28,94.26 ; 19.63,73.3 GND1.1 ; GND1.1 20.85,72.08 ; GND1.1 20.85,74.53 ; GND1.1 22.08,73.3 ; 107.74,62.99 J13.2 ; J13.2 109.58,62.99 ; J13.2 108.66,62.08 ; J13.2 108.66,63.91 ; J6.2 106.61,88.01 ; J6.2 102.44,88.01 ; J6.2 104.52,85.93 ; J6.2 104.52,90.1 ; 111.9,13.74 J2.4 ; J2.4 113.54,13.74 ; J2.4 112.72,12.92 ; JP6.10 94.36,96.14 ; JP6.10 94.36,94.26 ; JP6.10 95.3,95.2 ; JP6.10 93.42,95.2 ; U2.4 90.49,71.83 ; U2.4 89.61,72.71 ; U2.4 88.73,71.83 ; U2.4 89.61,70.95 ; 21.28,12.92 J4.4 ; J4.4 22.1,13.74 ; J4.4 20.46,13.74 ; 51.76,12.92 J3.4 ; J3.4 50.94,13.74 ; J3.4 52.58,13.74 ; J5.7 79.56,15.24 ; J5.7 78.74,14.42 ; J5.7 78.74,16.06 ; J5.7 77.92,15.24 ; JP6.2 84.2,96.14 ; JP6.2 85.14,95.2 ; JP6.2 83.26,95.2 ; JP6.2 84.2,94.26 ; J4.7 17.78,16.06 ; J4.7 17.78,14.42 ; J4.7 18.6,15.24 ; J4.7 16.96,15.24 ; 47.44,15.24 J3.7 ; J3.7 48.26,14.42 ; J3.7 49.08,15.24 ; J3.7 48.26,16.06 ; 91.82,94.26 JP6.8 ; JP6.8 91.82,96.14 ; JP6.8 90.88,95.2 ; JP6.8 92.76,95.2 ; J5.4 83.06,13.74 ; J5.4 81.42,13.74 ; J5.4 82.24,12.92 ; 62.66,84.36 J1.7 ; J1.7 63.48,85.18 ; J1.7 63.48,83.55 ; J1.7 64.3,84.36 ; JP6.4 87.68,95.2 ; JP6.4 86.74,94.26 ; JP6.4 85.8,95.2 ; JP6.4 86.74,96.14 ; 101.52,41.43 GND2.1 ; GND2.1 102.74,40.21 ; GND2.1 102.74,42.65 ; GND2.1 103.96,41.43 ; J2.7 109.22,16.06 ; J2.7 110.04,15.24 ; J2.7 109.22,14.42 ; J2.7 108.4,15.24
  BOTTOM w0.305: 67.65,59.95 C3.2 ; C3.2 68.28,60.48 ; C3.2 69.09,59.89 ; C3.2 68.91,59.95 ; C3.2 68.28,59.42 ; C48.2 58.59,14.15 ; C48.2 57.33,14.15 ; C48.2 v1(57.96,14.78) ; C66.2 v1(22.75,16.62) ; C66.2 22.22,17.42 ; C66.2 22.75,18.05 ; C66.2 23.28,17.42 ; 66.09,58.89 C32.2 ; C32.2 v1(66.42,59.31) ; C32.2 66.75,58.89 ; C46.2 v1(119.94,15.42) ; 100.61,67.87 R23.2 ; R23.2 101.15,68.5 ; R23.2 100.61,69.13 ; R23.2 100.08,68.5 ; JP6.8 92.76,95.2 ; JP6.8 91.82,96.14 ; JP6.8 90.88,95.2 ; 102.74,40.21 GND2.1 ; GND2.1 102.74,42.65 ; GND2.1 103.96,41.43 ; GND2.1 101.52,41.43 ; C59.2 89.05,14.15 ; C59.2 87.79,14.15 ; C59.2 v1(88.42,14.94) ; C77.2 87.7,21.79 ; C77.2 86.44,21.79 ; C77.2 v1(87.07,20.95) ; C75.2 53.46,18.03 ; C75.2 52.93,17.4 ; C75.2 53.99,17.4 ; C75.2 v1(53.46,16.73) ; 84.76,74.12 R40.1 ; R40.1 84.76,75.38 ; R40.1 84.23,74.75 ; R40.1 85.29,74.75 ; 22.1,13.74 J4.4 20.46,13.74 ; 67.31,43.24 C21.2 ; C21.2 67.64,42.91 ; C21.2 v1(68.19,43.24) ; JP6.6 90.22,95.2 ; JP6.6 89.28,96.14 ; JP6.6 88.34,95.2 ; 10.59,14.74 C50.2 ; C50.2 11.12,15.37 ; C50.2 10.06,15.37 ; C50.2 v2(9.88,15.34) ; C50.2 10.59,16 ; C57.2 29.64,14.1 ; C57.2 v2(29.01,15.11) ; C57.2 28.38,14.1 ; 64.34,47.21 C23.2 64.67,47.54 ; C8.2 66.09,53.45 ; C8.2 65.43,53.45 ; C8.2 65.76,53.12 ; 62.89,53.55 C22.2 ; C22.2 63.55,53.55 ; C22.2 63.22,53.22 ; 83.06,13.74 J5.4 81.42,13.74 ; C11.2 61.51,54.11 ; C11.2 61.19,53.78 ; C11.2 60.86,54.11 ; 78.74,14.42 J5.7 ; J5.7 78.74,16.06 ; J5.7 79.56,15.24 ; J5.7 77.92,15.24 ; 64.14,54.26 C30.2 63.8,53.93 ; 59.6,54.99 C15.2 ; C15.2 v1(59.18,55.32) ; C15.2 59.6,55.65 ; 107.67,23.29 R37.2 ; R37.2 108.2,23.59 107.77,24.02 v1(107.72,24.02) ; R37.2 108.73,23.29 ; 97.31,54.56 R24.1 ; R24.1 97.84,53.93 ; R24.1 98.53,54.56 v1(98.58,54.61) ; R24.1 97.84,55.19 ; 24.95,21.94 C69.2 ; C69.2 26.21,21.94 ; C69.2 v2(25.58,21.01) ; 93.42,95.2 JP6.10 ; JP6.10 94.36,96.14 ; JP6.10 95.3,95.2 ; J6.3 109.32,93.35 ; J6.3 107.24,91.26 ; J6.3 111.41,91.26 ; J6.3 109.32,89.18 ; JP6.4 86.74,96.14 ; JP6.4 87.68,95.2 ; JP6.4 86.74,94.26 ; JP6.4 85.8,95.2 ; 19.63,73.3 GND1.1 ; GND1.1 22.08,73.3 ; GND1.1 20.85,74.53 ; GND1.1 20.85,72.08 ; 60.02,53.17 C16.2 ; C16.2 60.35,53.5 ; C16.2 59.69,53.5 ; C40.2 v1(101.42,15.19) ; C40.2 102.71,15.19 ; C40.2 102.18,14.56 ; C40.2 102.18,15.82 ; 108.66,62.08 J13.2 ; J13.2 107.74,62.99 ; J13.2 109.58,62.99 ; J13.2 108.66,63.91 ; C56.2 31.31,14.13 ; C56.2 30.05,14.13 ; C56.2 30.68,14.66 ; C56.2 v2(30.71,15.11) ; 66.58,48.18 C6.2 ; C6.2 66.91,47.85 ; C6.2 66.91,48.51 ; C17.2 59.42,46.34 v1(59.11,46.02) C13.2 ; C17.2 60.2,46.01 ; C17.2 60.53,46.34 ; C14.2 68.66,46.9 ; C14.2 v1(68.33,46.48) ; C14.2 68,46.9 ; C51.2 v1(71.12,14.99) ; C51.2 72.33,14.99 ; C51.2 71.8,15.62 ; C51.2 71.8,14.36 ; C1.2 62.4,60.4 ; C1.2 61.87,59.77 ; C1.2 v1(61.29,60.4) ; C1.2 61.87,61.03 ; C12.2 67.33,54.71 ; C12.2 67,55.04 ; C12.2 67,54.19 ; R30.2 17.21,23.57 ; R30.2 16.15,23.57 ; R30.2 16.68,24.2 ; R30.2 v2(16.69,24.66) ; R30.2 16.68,22.94 ; C78.2 v1(83.84,16.63) ; C78.2 83.84,17.95 ; C78.2 83.31,17.32 ; C78.2 84.37,17.32 ; C10.2 64.58,54.35 ; C80.2 v1(117.75,21.03) ; C80.2 118.38,21.89 ; C80.2 117.12,21.89 ; C31.2 53.94,48.86 ; C31.2 54.92,47.78 ; C31.2 52.83,47.78 ; C31.2 53.94,46.7 ; C31.2 53.95,46.38 ; 100.63,64.65 R39.1 ; R39.1 100.63,65.91 ; R39.1 100.1,65.28 ; R39.1 101.17,65.28 ; R17.2 v1(121.74,14.3) ; 91.22,14.15 R20.2 ; R20.2 v1(91.85,14.91) ; R20.2 92.48,14.15 ; 46.43,23.29 R31.2 ; R31.2 47.49,23.29 ; R31.2 v1(46.96,24.05) ; 83.26,95.2 JP6.2 ; JP6.2 84.2,96.14 ; JP6.2 84.2,94.26 ; JP6.2 85.14,95.2 ; 56.29,56.92 R21.1 ; R21.1 57.35,56.92 ; R21.1 v1(56.82,57.66) ; 66.53,46.91 C7.2 ; C7.2 66.86,46.58 ; C7.2 66.86,47.49 ; C72.2 57.3,21.97 ; C72.2 v1(56.67,21.11) ; C72.2 56.04,21.97 ; 60.07,49.99 60.09,50 C33.2 ; U2.4 90.55,71.83 ; U2.4 89.61,70.89 ; U2.4 89.61,72.77 ; U2.4 88.67,71.83 ; 113.54,13.74 J2.4 111.9,13.74 ; 59.09,14.15 C49.2 ; C49.2 60.35,14.15 ; C49.2 v1(59.72,14.91) ; C41.2 v1(40.61,15.27) ; C41.2 41.83,15.32 ; C41.2 41.3,15.95 ; C41.2 40.76,15.32 ; C41.2 41.3,14.69 ; C81.2 v1(114.57,16.74) ; C81.2 114.57,18.03 ; C81.2 115.11,17.4 ; C81.2 114.04,17.4 ; 60.89,14.15 R18.2 ; R18.2 62.15,14.15 ; R18.2 v1(61.52,14.83) ; 89.46,14.15 C58.2 ; C58.2 v1(90.09,14.88) ; C58.2 90.72,14.15 ; 102.44,88.01 J6.2 ; J6.2 104.52,90.1 ; J6.2 104.52,85.93 ; J6.2 106.61,88.01 ; v1(54.99,52.55) 54.61,52.93 C18.2 ; 62.56,53.81 C26.2 62.23,54.14 ; 60.23,59.77 C2.2 ; C2.2 59.7,60.4 ; C2.2 v1(60.81,60.4) ; C2.2 60.23,61.03 ; 62.64,47.21 C34.2 62.31,47.54 ; R41.1 84.76,69.84 ; R41.1 85.29,69.22 ; R41.1 84.76,68.59 ; R41.1 84.23,69.22 ; 17.78,14.42 J4.7 ; J4.7 17.78,16.06 ; J4.7 18.6,15.24 ; J4.7 16.96,15.24 ; 72.78,44.15 C5.2 ; C5.2 74.64,44.15 ; C5.2 73.71,43.32 ; C5.2 73.71,44.98 ; R19.2 27.99,14.1 ; R19.2 27.36,14.63 ; R19.2 v2(27.38,15.11) ; R19.2 26.73,14.1 ; 65.84,47.59 C29.2 66.17,47.26 ; 60.14,52.27 C27.2 60.47,51.94 ; C20.2 67.43,57.89 ; C20.2 v1(67.94,57.56) ; C20.2 67.43,57.23 ; C19.2 v1(66.87,43.24) ; C19.2 66.07,43.24 ; C19.2 66.4,42.91 ; 109.22,14.42 J2.7 ; J2.7 110.04,15.24 ; J2.7 109.22,16.06 ; J2.7 108.4,15.24 ; C18.2 53.92,54.02 ; C18.2 53.92,51.85 ; C18.2 53.14,52.93 v1(52.86,52.65) ; J1.7 64.3,84.36 ; J1.7 62.66,84.36 ; J1.7 63.48,85.18 ; J1.7 63.48,83.55 ; 61.24,47.54 C25.2 60.91,47.21 ; C9.2 60.17,48.89 ; 76.98,23.01 R35.2 ; R35.2 77.52,23.64 ; R35.2 78.05,23.01 ; v1(65.84,58.78) 65.66,58.6 C24.2 ; J3.7 48.26,16.06 ; J3.7 48.26,14.42 ; J3.7 47.44,15.24 ; J3.7 49.08,15.24 ; 60.67,50.9 C28.2 ; C28.2 60.67,51.56 ; C28.2 61,51.23 ; C47.2 v1(119.94,17.18)
  BOTTOM w0.813: C70.2 13.28,31.3 ; C70.2 14.77,30.02 ; C70.2 11.8,30.02 ; C70.2 13.28,28.74 ; C76.2 75.52,29.95 ; C76.2 72.56,29.95 ; C76.2 74.04,28.67 ; C76.2 74.04,31.23 ; 42.03,29.92 C71.2 ; C71.2 44.99,29.92 ; C71.2 43.51,28.64 ; C71.2 43.51,31.2 ; C79.2 106.13,30 ; C79.2 103.17,30 ; C79.2 104.65,28.72 ; C79.2 104.65,31.28
  vias: v1(14.43,44.15) v1(14.48,57) v1(14.63,46.18) v1(16.94,62.46) v1(17.2,47.07) v1(17.63,67.94) v1(17.58,29.67) v1(17.96,49) v1(18.44,41.58) v1(19,35.64) v1(20.09,51.56) v1(20.35,44.63) v1(20.35,42.37) v1(20.45,49.78) v1(21.89,67.79) v1(22.33,52.35) v1(22.48,60.86) v1(23.44,45.57) v1(23.67,40.13) v1(24.03,57) v1(24.36,47.78) v1(25.55,28.57) v1(26.64,48.62) v1(27.28,50.88) v1(28.96,51.18) v1(29.46,33.15) v1(29.82,20.88) v1(30.07,46.2) v1(31.27,22.02) v1(31.45,18.52) v1(31.62,29.31) v1(32.89,20.7) v1(33.58,17.45) v1(34.14,31.75) v1(34.54,43.13) v1(34.87,51.1) v1(35.36,19.79) v1(35.76,24.26) v1(35.99,28.35) v1(36.32,54.36) v1(36.65,34.34) v1(38.4,46.76) v1(39.52,37.72) v1(39.6,52.12) v1(40.94,54.33) v1(41.33,63.2) v1(41.33,39.8) v1(41.83,49.81) v1(42.88,72.11) v1(43.51,61.21) v1(43.69,52.07) v1(43.84,46.1) v1(45.09,49.86) v1(45.47,40.79) v1(46.3,55.32) v1(47.04,74.37) v1(47.57,47.45) v1(47.78,52.81) v1(49.43,55.32) v1(49.83,47.78) v1(49.86,77.09) v1(50.37,44.02) v1(51.46,45.34) v1(51.71,53.01) v1(52.35,48.34) v1(52.6,55.32) v1(53.06,34.95) v1(53.39,71.75) v1(53.62,20.29) v1(54.31,41.99) v1(54.41,26.85) v1(55.12,48.26) v1(55.52,36.68) v1(55.55,32.82) v1(56.08,74.07) v1(56.39,43.31) v1(56.9,26.39) v1(57.3,21.11) v1(57.94,21.74) v1(57.94,21.11) v1(58.27,40) v1(58.32,35.81) v1(58.34,32.89) v1(58.27,29.62) v1(58.27,18.19) v1(58.65,73.15) v1(60.27,26.95) v1(60.5,30.76) v1(60.58,40.64) v1(60.55,37.72) v1(60.6,34.04) v1(61.11,17.37) v1(61.37,64.85) v1(61.54,73.56) v1(61.49,68.99) v1(61.47,52.7) v1(61.47,52.07) v1(61.47,51.43) v1(61.47,50.8) v1(61.47,50.16) v1(61.47,49.53) v1(61.47,48.89) v1(61.9,78.84) v1(61.9,25.35) v1(61.9,20.22) v1(61.98,28.14) v1(62.23,52.83) v1(62.23,48.77) v1(62.51,39.88) v1(62.74,34.16) v1(62.79,81.41) v1(62.84,37.69) v1(62.87,52.83) v1(62.87,48.77) v1(63.2,77.09) v1(63.3,23.9) v1(63.5,52.83) v1(63.5,48.77) v1(63.55,36.02) v1(63.83,32.21) v1(63.93,75.06) v1(64.14,52.83) v1(64.14,48.77) v1(64.34,79.2) v1(64.26,16.56) v1(64.41,66.14) v1(64.47,70.33) v1(64.49,61.06) v1(64.64,40.18) v1(64.74,25.37) v1(64.77,52.83) v1(64.77,48.77) v1(65.05,81.86) v1(65.25,30.07) v1(65.53,52.7) v1(65.53,52.07) v1(65.53,51.43) v1(65.53,50.8) v1(65.53,50.16) v1(65.53,49.53) v1(65.53,48.89) v1(65.66,41.83) v1(65.79,36.02) v1(66.5,73.89) v1(66.62,27.46) v1(67.26,68.43) v1(68.05,20.35) v1(68.2,78.87) v1(68.3,61.7) v1(68.43,63.98) v1(68.68,66.01) v1(68.83,43.84) v1(68.88,38.28) v1(68.86,31.78) v1(68.86,27.2) v1(69.42,35.36) v1(69.65,41.91) v1(69.62,24.21) v1(69.85,22.22) v1(70.05,18.8) v1(70.18,72.47) v1(70.18,16) v1(70.48,66.6) v1(70.61,40.69) v1(70.66,19.94) v1(72.42,47.27) v1(72.44,33.73) v1(72.75,71.86) v1(72.87,74.24) v1(73.15,38.79) v1(73.46,85.42) v1(73.79,69.77) v1(74.14,55.5) v1(74.68,81.15) v1(74.98,47.32) v1(75.01,41.43) v1(75.92,58.27) v1(76.1,73.66) v1(77.65,31.34) v1(77.9,28.5) v1(79.1,83.85) v1(80.29,85.95) v1(81.81,70.97) v1(81.81,31.22) v1(81.86,76.86) v1(82.09,55.42) v1(82.19,81.94) v1(82.22,28.7) v1(82.75,89.64) v1(82.78,47.6) v1(83.74,23.77) v1(83.95,33.83) v1(84.3,59.16) v1(84.63,20.22) v1(85.04,84.45) v1(87.48,17.6) v1(87.71,20.95) v1(88.04,35.36) v1(88.04,31.29) v1(88.11,28.7) v1(88.34,21.59) v1(88.34,20.95) v1(90.68,66.98) v1(90.78,64.41) v1(91.95,21.62) v1(91.97,83.82) v1(92.38,18.57) v1(92.66,23.95) v1(92.91,39.24) v1(92.94,31.24) v1(93.09,36.07) v1(93.17,28.32) v1(93.5,21.29) v1(94.11,72.47) v1(94.84,17.3) v1(95.58,73.05) v1(96.44,37.62) v1(96.85,31.24) v1(97.71,23.14) v1(97.97,24.99) v1(98.35,87.73) v1(98.68,33.76) v1(99.57,21.92) v1(100.33,43.05) v1(100.71,25.22) v1(101.19,69.7) v1(102.36,73.76) v1(103.07,34.65) v1(105.51,62.69) v1(107.85,26.9) v1(109.78,69.62) v1(109.98,33.22) v1(112.73,47.98) v1(114.43,65.1) v1(114.94,29.11) v1(116.56,82.47) v1(118.39,21.03) v1(118.54,47.45) v1(119,80.47) v1(119.02,21.67) v1(119.02,21.03) v1(119.51,70.41) v1(119.81,40.72) v1(122.4,74.04) v1(124.05,83.49) v1(124.51,64.9) v2(26.21,21.01) v2(26.85,21.77) v2(26.85,21.01) v2(32.66,66.75) v2(32.66,65.99) v2(32.66,65.23) v2(32.66,64.47) v2(33.43,66.75) v2(33.43,64.47) v2(34.19,66.75) v2(34.19,64.47) v2(34.95,66.75) v2(34.95,65.99) v2(34.95,65.23) v2(34.95,64.47) v2(110.9,42.52) v2(110.9,41.76) v2(110.9,41) v2(110.9,40.23) v2(110.9,39.47) v2(110.9,38.71) v2(110.9,37.95) v2(110.9,37.19) v2(110.9,36.42) v2(111.66,42.52) v2(111.66,36.42) v2(112.42,42.52) v2(112.42,36.42) v2(113.18,42.52) v2(113.18,36.42) v2(113.94,42.52) v2(113.94,36.42) v2(114.71,42.52) v2(114.71,36.42) v2(115.47,42.52) v2(115.47,36.42) v2(116.23,42.52) v2(116.23,41.76) v2(116.23,41) v2(116.23,40.23) v2(116.23,39.47) v2(116.23,38.71) v2(116.23,37.95) v2(116.23,37.19) v2(116.23,36.42)
GND_EARTH: length 100.6
  TOP w0.305: C39.1 v1(73.51,90.53) ; R15.1 v1(73.58,88.8) ; C38.1 v1(73.41,92.25)
  BOTTOM w0.305: 24.35,9.65 J4.11 ; J4.11 22.27,11.74 ; J4.11 24.35,13.83 ; J4.11 26.44,11.74 ; 59.72,12.32 C49.1 ; C49.1 59.09,12.85 ; C49.1 60.35,12.85 ; C47.1 118.64,17.04 ; C47.1 118.11,16.41 ; C47.1 118.64,15.78 ; C47.1 119.17,16.41 ; 26.73,12.8 R19.1 ; R19.1 27.99,12.8 ; R19.1 27.36,12.27 ; 30.68,12.3 C56.1 ; C56.1 30.05,12.83 ; C56.1 31.31,12.83 ; R20.1 92.48,12.85 ; R20.1 91.85,12.32 ; R20.1 91.22,12.85 ; 70.08,11.74 J5.10 ; J5.10 74.25,11.74 ; J5.10 72.17,9.65 ; J3.11 56.92,11.74 ; J3.11 54.83,9.65 ; J3.11 52.75,11.74 ; J3.11 54.83,13.83 ; 57.33,12.85 C48.1 ; C48.1 58.59,12.85 ; C48.1 57.96,12.32 ; 57.46,88.98 J1.11 ; J1.11 55.37,91.07 ; J1.11 59.55,91.07 ; J1.11 57.46,93.15 ; 83.23,11.74 J5.11 ; J5.11 87.4,11.74 ; J5.11 85.31,13.83 ; J5.11 85.31,9.65 ; R17.1 121.72,16.76 ; R17.1 121.72,15.7 ; R17.1 121.09,16.23 ; R17.1 122.35,16.23 ; 28.38,12.8 C57.1 ; C57.1 29.01,12.27 ; C57.1 29.64,12.8 ; R18.1 62.15,12.85 ; R18.1 60.89,12.85 ; R18.1 61.52,12.32 ; J2.10 104.73,11.74 ; J2.10 102.65,9.65 ; J2.10 100.56,11.74 ; 113.71,11.74 J2.11 ; J2.11 115.79,13.83 ; J2.11 117.88,11.74 ; J2.11 115.79,9.65 ; 69.5,88.98 J1.10 ; J1.10 69.5,93.15 ; J1.10 67.41,91.07 ; J1.10 71.58,91.07 ; 118.11,14.66 C46.1 ; C46.1 118.64,15.29 ; C46.1 119.17,14.66 ; C46.1 118.64,14.03 ; 87.79,12.85 C59.1 ; C59.1 89.05,12.85 ; C59.1 88.42,12.32 ; 9.12,11.74 J4.10 ; J4.10 13.29,11.74 ; J4.10 11.21,9.65 ; 39.6,11.74 J3.10 ; J3.10 41.69,9.65 ; J3.10 43.77,11.74 ; C58.1 90.72,12.85 ; C58.1 89.46,12.85 ; C58.1 90.09,12.32
VBUS_DS1: length 5
  BOTTOM w0.508: J4.1 13.42,13.74 11.89,15.27 C50.1 FB5.1
VBUS_DS2: length 4.8
  BOTTOM w0.508: J3.1 44.1,13.74 42.67,15.17 C41.1 FB4.1
VBUS_DS3: length 4.9
  BOTTOM w0.508: J5.1 74.25,13.74 73.1,14.89 C51.1 FB6.1
VBUS_DS4: length 5.1
  BOTTOM w0.508: J2.1 104.83,13.74 103.48,15.09 C40.1 103.48,15.92 103.86,16.3 FB3.1
VDD11: length 21.2
  TOP w0.305: U1.13 v1(59.5,48.55) ; v1(67.03,43.87) 66.75,44.15 U1.31 ; U1.57 v1(63.25,54.76) ; U1.51 v1(66.25,57.67) ; U1.5 v1(59.51,52.55) ; U1.28 v1(65.25,46.87) ; U1.8 v1(59.52,51.05) ; U1.21 v1(61.75,46.92)
  BOTTOM w0.305: C29.1 65.46,46.66 v1(65.25,46.87) 65,46.62 64.68,46.62 C23.1 ; C27.1 59.54,52.52 v1(59.51,52.55) ; C20.1 66.36,57.56 v1(66.25,57.67) ; v1(66.25,57.67) 66.42,57.84 C32.1 ; v1(66.25,57.67) 66.23,57.68 C24.1 ; C34.1 62.15,46.61 61.85,46.92 v1(61.75,46.92) 61.44,46.61 C25.1 ; C28.1 59.7,51.23 v1(59.52,51.05) 59.49,51.02 C33.1 ; C22.1 63.22,54.74 ; 63.22,54.74 C26.1 ; 63.22,54.74 v1(63.25,54.76) 63.5,54.76 63.6,54.86 C30.1 ; C21.1 67.06,43.84 v1(67.03,43.87) 67.01,43.84 C19.1
  vias: v1(56.24,55.09) v1(56.31,46.25) v1(56.31,45.62) v1(56.87,55.09) v1(56.95,46.25) v1(56.95,45.62) v1(57.51,55.09) v1(57.58,46.25) v1(57.58,45.62) v1(58.14,55.09) v1(58.22,46.25) v1(58.22,45.62)
VDD33: length 16.1
  TOP w0.305: U1.16 v1(59.6,47.05) ; U1.52 v1(65.75,54.73) ; U1.34 v1(67.51,47.55) ; U1.63 v1(60.25,54.71)
  BOTTOM w0.305: C16.1 60.02,54.36 60.25,54.58 v1(60.25,54.71) ; C14.1 67.56,47.5 v1(67.51,47.55) ; v1(60.25,54.71) 60.2,54.76 C15.1 ; v1(60.25,54.71) C11.1 ; C13.1 59.62,47.07 59.61,47.06 ; C8.1 65.76,54.72 ; 65.76,54.72 v1(65.75,54.73) 65.74,54.71 C10.1 ; 65.76,54.72 65.77,54.71 C12.1 ; C6.1 v1(67.51,47.55) ; v1(67.51,47.55) 67.46,47.5 C7.1 ; v1(73.71,46.96) C5.1 v1(74.78,46.02) ; 59.61,47.06 C9.1 ; 59.61,47.06 v1(59.6,47.05) 59.61,47.04 60.1,47.04 C17.1
  vias: v1(76.84,47.78) v1(76.84,47.14) v1(76.84,46.51) v1(76.84,45.87) v1(76.84,45.24) v1(77.47,47.78) v1(77.47,45.24) v1(78.11,47.78) v1(78.11,45.24)
1P1V_FB: length 3.9
  TOP w0.305: R34.1 R33.2 U6.16
1P1V_SS: length 2.3
  TOP w0.305: U6.15 38.18,66.93 38.23,66.88 R32.1
AUTOENZ/BB_BMCONFIG1: length 36.4
  TOP w0.305: U1.45 71.16,53.05 v1(71.42,53.31)
  BOTTOM w0.305: v1(71.42,53.31) 72.26,54.15 88.67,54.15 89.69,55.17 89.69,65.58 J10.1
AUTOENZ/BB_BMCONFIG1_2: length 16.9
  TOP w0.305: J10.2 87.86,71.12 88.78,70.2 88.78,68.73 89.36,68.15 SW2.1 91.47,68.15 92.08,67.54 92.08,61.06 91.54,60.53 SW2.7
AUTOENZ_PD/BB_BMCONFIG1_PD: length 2.2
  TOP w0.305: SW2.16 v1(98.22,68.15)
  BOTTOM w0.305: v1(98.22,68.15) 98.58,68.5 R23.1
AUTOENZ_PU/BB_BMCONFIG1_PU: length 3.1
  TOP w0.305: SW2.10 97.49,60.53 99.03,58.98 R48.1
BATEN0: length 2.6
  TOP w0.305: SW1.12 v1(95.76,50.37)
  BOTTOM w0.305: R6.1 96.52,49.61 v1(95.76,50.37)
BATEN1: length 2.8
  TOP w0.305: v1(95.73,48.74) 96.09,49.1 SW1.11
  BOTTOM w0.305: R7.1 96.52,47.96 v1(95.73,48.74)
BATEN2: length 3
  TOP w0.305: SW1.10 96.29,47.83 v1(95.73,47.27)
  BOTTOM w0.305: v1(95.73,47.27) 96.57,46.43 R8.1
BATEN3: length 3.2
  TOP w0.305: v1(95.73,45.54) 96.17,45.98 96.4,45.98 96.98,46.56 SW1.9
  BOTTOM w0.305: R9.1 96.57,44.7 v1(95.73,45.54)
BOARD_1P1V: length 6.3
  TOP w0.305: U6.1 29.66,66.93 29.64,66.95 ; U6.18 33.83,69.24
  L3_VCC w0.813: J9.2 40.51,60.96 ; J9.2 40.51,58.82 ; J9.2 39.44,59.89 ; J9.2 41.58,59.89
  vias: v1(27.25,71.5) v1(27.25,70.87) v1(27.25,70.23) v1(27.89,71.5) v1(27.89,70.87) v1(27.89,70.23) v1(28.52,71.5) v1(28.52,70.87) v1(28.52,70.23) v1(29.16,71.5) v1(29.16,70.87) v1(29.16,70.23) v1(29.79,71.5) v1(29.79,70.87) v1(29.79,70.23)
BOARD_3P3V: length 29.4
  TOP w0.305: R27.1 v1(60.53,22.35) ; U6.5 30.93,64.01 30.94,64.01 ; 36.75,64.01 36.73,64.03 U6.11 ; R26.1 v1(30.12,22.25) ; C4.1 U2.8 99.31,79.45 101.12,77.64 R10.1 v1(101.78,76.91) ; R48.2 v1(101.93,58.98) ; R36.1 v1(119.15,27.15) ; R45.1 v1(94.34,85.9) ; R42.1 v1(86.77,85.75) ; R43.1 v1(89.31,85.9) ; R29.1 v1(91.03,22.25) ; R44.1 v1(91.82,85.9)
  L3_VCC w0.305: 96.35,79.45 U2.8 ; U2.8 97.23,80.33 ; U2.8 97.23,78.57 ; U2.8 98.11,79.45
  L3_VCC w0.813: J7.2 88.04,42.9 ; J7.2 86.97,43.97 ; J7.2 85.9,42.9 ; J7.2 86.97,41.83
  BOTTOM w0.305: R25.2 v1(101.47,66.88) ; R5.2 98.53,51.26 v1(98.58,51.31) ; v1(98.55,52.96) 98.5,52.91 R4.2 ; R6.2 98.42,49.61 v1(98.48,49.66) ; v1(98.53,56.26) 98.48,56.21 R22.2 ; R38.2 v1(101.32,63.68) ; R8.2 98.42,46.3 v1(98.48,46.35) ; v1(98.6,44.7) 98.55,44.65 R9.2 ; v1(98.5,48.01) 98.45,47.96 R7.2
  vias: v1(34.85,61.16) v1(34.85,60.53) v1(34.85,59.89) v1(34.85,59.26) v1(35.48,61.16) v1(35.48,60.53) v1(35.48,59.89) v1(35.48,59.26) v1(36.12,61.16) v1(36.12,60.53) v1(36.12,59.89) v1(36.12,59.26) v1(36.75,61.16) v1(36.75,60.53) v1(36.75,59.89) v1(36.75,59.26) v1(46.91,33.55) v1(51.69,33.25) v1(80.54,34.16) v1(103.4,55.65) v1(103.4,54.89) v1(103.4,54.13) v1(104.17,55.65) v1(104.17,54.89) v1(104.17,54.13) v1(104.93,55.65) v1(104.93,54.89) v1(105.69,55.65) v1(105.69,54.89) v1(105.69,54.13) v1(106.45,55.65) v1(106.45,54.89) v1(106.45,54.13)
BOARD_5V: length 20.6
  TOP w0.305: 120.93,55.74 C82.1 ; C82.1 120.93,57.9 ; C82.1 119.95,56.82 ; U9.3 v1(88.08,18.28) ; U8.2 v1(56.9,18.38) ; U8.3 v1(57.55,18.41) ; U9.2 v1(87.43,18.28) ; U7.3 v1(26.56,18.26) ; U10.3 v1(118.71,18.37) ; U10.2 v1(118.06,18.39) ; U7.2 v1(25.91,18.24)
  L3_VCC w0.813: 113.72,75.3 SW3.2 ; SW3.2 117.13,75.3 ; SW3.2 115.42,77 ; SW3.2 115.42,73.59
  BOTTOM w0.305: C75.1 v1(55.37,17.4) ; C81.1 v1(116.41,17.4) ; C78.1 v1(85.65,17.32) ; C66.1 v1(24.66,17.42)
  vias: v1(112.85,65.74) v1(116.13,58.17) v1(116.13,57.53) v1(116.13,56.9) v1(116.13,56.26) v1(116.76,58.17) v1(116.76,57.53) v1(116.76,56.9) v1(116.76,56.26) v1(117.4,58.17) v1(117.4,57.53) v1(117.4,56.9) v1(117.4,56.26) v1(118.03,58.17) v1(118.03,57.53) v1(118.03,56.9) v1(118.03,56.26) v1(118.67,58.17) v1(118.67,57.53) v1(118.67,56.9) v1(118.67,56.26) v1(122.1,29.13) v1(123.16,32.11)
CAP_DN_TXM1: length 7.1
  TOP w0.229: C52.1 15.08,20.99 14.94,20.85 14.94,18.26 15.6,17.6 15.6,17.17 14.94,16.51 14.94,16.08 J4.8
CAP_DN_TXM2: length 7.1
  TOP w0.229: J3.8 45.42,16.08 45.42,16.54 46.08,17.2 46.08,17.78 45.42,18.43 45.42,20.85 45.56,20.99 C43.1
CAP_DN_TXM3: length 6.5
  TOP w0.229: J5.8 75.91,16.07 75.91,21.25 C53.1
CAP_DN_TXM4: length 6.6
  TOP w0.229: C42.1 106.38,21.25 106.38,16.09 J2.8
CAP_DN_TXP1: length 6.5
  TOP w0.229: J4.9 14.61,16.07 14.61,21.25 C54.1
CAP_DN_TXP2: length 6.5
  TOP w0.229: J3.9 45.09,16.07 45.09,21.25 C45.1
CAP_DN_TXP3: length 6.6
  TOP w0.229: C55.1 75.58,21.25 75.58,16.08 J5.9
CAP_DN_TXP4: length 6.5
  TOP w0.229: C44.1 106.05,21.25 106.05,16.07 J2.9
CAP_UP_TXM: length 15.1
  TOP w0.229: C36.1 66.46,78.24 66.46,79.27 70.31,83.12 70.31,85.09 69.37,86.03 68.84,86.03 68.67,85.85 68.67,85.47 68.49,85.29 68.23,85.29 68.06,85.47 68.06,85.85 67.88,86.03 67.52,86.03 67.02,85.53 67.02,84.97 67.63,84.36 J1.5
CAP_UP_TXP: length 15.1
  TOP w0.229: J1.6 66.69,85.07 66.69,85.66 67.39,86.36 69.5,86.36 70.64,85.23 70.64,82.98 66.79,79.14 66.79,78.24 C37.1
DN1_VBUS: length 4.1
  TOP w0.305: 26.57,24.51 26.56,24.51 U7.6 ; D5.1 v1(17.98,20.47) ; D5.1 v1(16.94,21.51) ; D5.1 v1(19.08,21.51)
  vias: v1(24.89,24.66) v1(25.53,24.66) v1(26.16,24.66)
DN2_VBUS: length 4.2
  TOP w0.305: D6.1 v1(48.31,20.4) ; D6.1 v1(47.22,21.51) ; D6.1 v1(49.35,21.51) ; U8.6 57.55,24.53 57.56,24.54
  vias: v1(55.63,24.43) v1(55.63,23.8) v1(55.63,23.16)
DN3_VBUS: length 4.5
  TOP w0.305: U9.6 88.08,24.54 88.06,24.56 ; D7.1 v1(79.83,21.39) ; D7.1 v1(78.87,20.27) ; D7.1 v1(77.77,21.39)
  BOTTOM w0.305: 74.04,23.29 C76.1
  vias: v1(85.78,24.31) v1(85.78,23.67) v1(85.78,23.04)
DN4_VBUS: length 4.2
  TOP w0.305: U10.6 118.71,24.71 118.72,24.71 ; D8.1 v1(109.5,20.47) ; D8.1 v1(110.41,21.51) ; D8.1 v1(108.38,21.51)
  vias: v1(116.64,24.49) v1(116.64,23.85) v1(116.64,23.22)
FULLPWRMGMTZ_PUP/BB_BMCONFIG0_P: length 2.5
  TOP w0.305: SW2.13 v1(98.2,64.34)
  BOTTOM w0.305: R38.1 99.36,63.78 98.82,64.33 98.72,64.33 98.7,64.34 v1(98.2,64.34)
FULLPWRMGMTZ_SS_UP/BB_BMCONFI_1: length 20.9
  TOP w0.305: U1.40 74.17,50.55 81.76,58.01 J12.1
FULLPWRMGMTZ_SS_UP/BB_BMCONFIG0: length 11.4
  TOP w0.305: SW2.4 88.7,64.34 88.44,64.08 88.44,62.31 88.35,62.21 88.34,62.2 J12.2 ; v1(83.39,62.33) 83.39,63.13 83.46,63.21 D2.1
  BOTTOM w0.305: J12.2 85.17,60.55 v1(83.39,62.33)
GANGED_HS_UP/BB_CONNECT: length 22.7
  TOP w0.305: U1.42 73.29,51.55 v1(84.63,62.89)
  BOTTOM w0.305: v1(84.63,62.89) 85.04,63.3 J11.1
GANGED_HS_UP/BB_CONNECT_2: length 8.7
  TOP w0.305: D3.1 83.57,69.8 85.27,68.1 85.27,67.26 J11.2 87.73,66.88 SW2.2
GANGED_PU/BB_CONNECT_PU: length 2.1
  TOP w0.305: SW2.15 v1(98.3,66.88)
  BOTTOM w0.305: v1(98.3,66.88) R25.1
GRSTZ: length 3.6
  TOP w0.305: U1.50 66.75,57.56 67.16,57.96 v1(67.21,58.39)
  BOTTOM w0.305: v1(67.21,58.39) 67.46,58.65 C3.1
OVERCUR1Z_TDI: length 114.6
  TOP w0.305: JP6.5 89.28,91.62 89.31,91.59 R43.2 88.58,87.71 88.57,87.71 88.39,87.71 88.19,87.5 88.19,84.66 86.72,83.19 85.04,83.19 82.8,80.95 82.8,76.17 71.88,65.25 71.88,54.64 v1(71.09,53.85) 70.8,53.55 U1.46 ; U7.5 28.49,23.56 28.51,23.55 R26.2 v1(29.95,23.55)
  BOTTOM w0.305: v1(71.09,53.85) 71.5,54.25 71.5,54.74 70.94,55.3 70.23,55.3 69.24,54.31 69.24,45.77 68.5,45.03 65.1,45.03 63.53,43.46 63.53,42.44 48.59,27.51 36.63,27.51 32.67,23.55 v1(29.95,23.55)
OVERCUR2Z_TMS: length 95.5
  TOP w0.305: U8.5 59.05,23.61 59.09,23.65 R27.2 v1(60.46,23.65) ; v1(83.92,88.62) 83.92,85.39 80.95,82.42 80.95,75.77 70.74,65.56 70.74,64.49 70.74,64.49 v1(70.74,54.38) 70.41,54.05 U1.47 ; R44.2 JP6.7
  BOTTOM w0.305: v1(70.74,54.38) 70,53.64 70,43 66.42,39.42 66.42,28.4 61.68,23.65 v1(60.46,23.65) ; JP6.7 91.82,91.62 91.69,91.49 91.69,91.41 90.93,90.65 84.86,90.65 83.92,89.71 v1(83.92,88.62)
OVERCUR3Z_TCK: length 106
  TOP w0.305: U1.44 71.37,52.55 71.65,52.83 v1(71.68,52.83) 73.08,54.23 73.08,65.13 83.74,75.79 83.74,79.93 85.83,82.02 93.01,82.02 95.78,84.79 95.78,87.02 95.06,87.74 R45.2 94.34,91.59 94.36,91.62 JP6.9 ; U9.5 89.61,23.51 89.64,23.55 R29.2 v1(91.09,23.55)
  BOTTOM w0.305: v1(91.09,23.55) 91.09,42.39 88.8,44.68 87.63,44.68 86.26,46.05 86.26,49.71 84.45,51.51 71.93,51.51 71.34,52.11 71.34,52.49 v1(71.68,52.83)
OVERCUR4Z: length 70.2
  TOP w0.305: v1(120.78,25.68) R36.2 119.89,24.74 119.36,24.21 U10.5 ; v1(72.09,52.37) 71.76,52.05 U1.43
  BOTTOM w0.305: v1(72.09,52.37) 87.6,52.37 93.52,46.46 93.52,45.47 100.13,38.86 104.14,38.86 108.83,34.18 117.61,34.18 120.78,31.01 v1(120.78,25.68)
PWRCTL_POL_PD: length 2.2
  TOP w0.305: SW2.14 v1(98.2,65.61)
  BOTTOM w0.305: R39.2 99,65.61 v1(98.2,65.61)
PWRCTL_POL_TDO: length 73.2
  TOP w0.305: R42.2 86.77,91.59 86.74,91.62 JP6.3 ; v1(90.55,65.61) SW2.3 88.7,65.61 87.71,64.62 85.84,64.62 85.52,64.3 85.52,64.24 85.14,63.86 85.14,62.43 73.76,51.05 U1.41
  BOTTOM w0.305: v1(90.55,65.61) 91.52,66.57 91.52,81.05 95.81,85.34 95.81,93.14 95,93.95 88.04,93.95 JP6.3
PWRON1_BATEN1: length 96.2
  TOP w0.305: U1.36 v1(70.62,48.55) 76.31,48.55 78.16,50.39 88.67,50.39 88.7,50.37 SW1.5 ; U7.4 v1(27.7,19.36)
  BOTTOM w0.305: v1(70.62,48.55) 70.62,42.1 67.56,39.04 67.56,26.9 62,21.34 59.82,21.34 59.23,21.92 59.23,26.47 57.56,28.14 54.51,28.14 52.88,26.52 40.06,26.52 32.9,19.36 v1(27.7,19.36)
PWRON2_BATEN2: length 58.7
  TOP w0.305: U8.4 v1(58.68,19.41) ; U1.35 70.42,48.05 v1(71.4,48.06) ; SW1.6 v1(84.25,49.1)
  BOTTOM w0.305: v1(58.68,19.41) 62.8,19.41 70.21,26.82 70.21,37.72 71.4,38.91 v1(71.4,48.06) 72.95,48.06 74.88,49.99 83.36,49.99 v1(84.25,49.1)
PWRON3_BATEN3: length 63.8
  TOP w0.305: U1.33 70.53,47.05 73.18,44.4 82.6,44.4 86.03,47.83 SW1.7 v1(90.55,47.83) ; U9.4 v1(89.3,19.31)
  BOTTOM w0.305: v1(89.3,19.31) 92.77,19.31 94.59,21.13 94.59,40.72 89.89,45.42 88.29,45.42 87.76,45.95 87.76,47.32 88.27,47.83 v1(90.55,47.83)
PWRON4_BATEN4: length 73
  TOP w0.305: SW1.8 v1(88.67,46.56) 86.03,46.56 83.11,43.64 72.82,43.64 71.01,45.45 U1.32 ; U10.4 v1(120,19.41)
  BOTTOM w0.305: v1(88.67,46.56) 90.53,46.56 99.54,37.54 102.54,37.54 108.36,31.72 116.99,31.72 120,28.72 v1(120,19.41)
